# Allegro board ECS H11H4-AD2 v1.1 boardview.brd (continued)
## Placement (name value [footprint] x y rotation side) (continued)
TP15  tp  [TP30_SMD]  35.48 41.86 0 top
TP16  tp  [TP30_SMD]  33.91 40.72 90 top
TP17  tp  [TP30_SMD]  35.48 40 90 top
TP18  tp  [TP30_SMD]  35.43 38.05 0 top
TP19  tp  [TP30_SMD]  60.43 37.08 90 top
TP20  tp  [TP30_SMD]  99.92 35.56 0 top
U1  azc099-04s-r7g-s-o  [SOT23_6P_2]  171.55 233.48 270 top
U2  azc099-04s-r7g-s-o  [SOT23_6P_2]  178.66 233.38 90 top
U3  az1045-04f-s-o  [FPC_4P10_R_1]  118.72 228.73 0 top
U4  az1045-04f-s-o  [FPC_4P10_R_1]  122.78 228.73 0 top
U5  u74lvc1g32g-af5-r-o  [SOT23_5P_1]  168.07 228.19 90 top
U6  u74lvc1g32g-af5-r-o  [SOT23_5P_1]  172.62 228.19 90 top
U7  it6516afn_qfn-40-o  [QFN40_PT04_E2201]  188.24 227.89 0 top
U8  azc099-04s-r7g-s-o  [SOT23_6P_2]  130.4 227.33 90 top
U9  az1045-04f-s-o  [FPC_4P10_R_1]  140.56 226.82 0 top
U10  az1045-04f-s-o  [FPC_4P10_R_1]  136.12 226.8 0 top
U11  azc099-04s-r7g-s-o  [SOT23_6P_2]  149.96 226.26 90 top
U12  esd3v3u4ulc-o  [FPC_4P10_R_1]  94.97 223.6 0 top
U13  esd3v3u4ulc-o  [FPC_4P10_R_1]  99.42 223.49 0 top
U14  azc099-04s-r7g-s-o  [SOT23_6P_2]  90.88 222.96 0 top
U15  up7537bsu8s  [PSOP8_W150_PT50_PAD-UP7719B_1]  105.71 213.41 270 top
U16  azc099-04s-r7g-s-o  [SOT23_6P_2]  61.57 213.36 180 top
U17  az1013-04s  [SOT23_6P_2]  75.29 212.6 0 top
U18  az1013-04s  [SOT23_6P_2]  70.92 212.55 0 top
U19  isl95858hrz  [QFN52_PT04_NCP61X1S_1]  165.07 211.2 180 top
U20  up7536ama8s  [SOT23_8P_1]  76.43 202.31 270 top
U21  rtl8111ga-cg  [QFN32_PT04_NCP81102]  51.77 201.53 270 top
U22  up1537  [DFN10_PT05_RT8015A_1]  95.22 198.37 180 top
U23  74lvc1g08gws  [SOT353_5P]  28.68 183.46 90 top
U24  isl95808  [DFN8_PT05_ISL6208_1]  189.71 177.8 0 top
U25  up0104ssw8-o  [PSOP8_W150_PT50_PAD-UP6281_1]  5.94 156.84 0 top
U26  apl3529a  [DFN8_NCP5359A_1]  71.6 147.57 270 top
U27  isl95808  [DFN8_PT05_ISL6208_1]  191.11 142.37 0 top
U28  nb671  [FCQFN16_RT7290A_NB669]  62.43 124.18 90 top
U29  74lvc1g14gw-o  [SOT353_5P]  183.26 117.35 0 top
U30  up7536ama8s  [SOT23_8P_1]  15.85 75.56 0 top
U31  up1740p  [QFN32_PT04_UP1740Q_2]  144.37 73.28 180 top
U32  azc099-04s-r7g-s-o  [SOT23_6P_2]  9.35 69.85 270 top
U33  up7537bsu8s  [PSOP8_W150_PT50_PAD-UP7719B_1]  10.13 63.88 90 top
U34  gs358sfs-o  [SOP8_W150_PT50]  176.54 59.7 0 top
U35  up1537  [DFN10_PT05_RT8015A_1]  125.07 53.47 90 top
U36  up0104ssw8  [PSOP8_W150_PT50_PAD-UP6281_1]  158.98 49.91 0 top
U37  5v2305nrgi8s-o  [QFN16_PT05_2D1X2D6MM]  97.13 42.42 270 top
U38  it8613e-bx  [TQFP64_PT04_F71808A]  111.99 34.04 0 top
U39  azc099-04s-r7g-s-o  [SOT23_6P_2]  13.06 31.34 270 top
U40  up7536ama8s  [SOT23_8P_1]  20.29 25.15 0 top
U41  74lvc1g14gw  [SOT353_5P]  51.66 19.38 90 top
U42  azc099-04s-r7g-s-o  [SOT23_6P_2]  11.28 17.65 270 top
U43  74aup1g08gf-o  [SON6_SOT891_PT035_74AUP1G08]  79.35 15.37 270 top
USB2_LAN  usbx2-lan-1000-6k/2k-speedtech  [RJ45_USB_22P-ICOTHING_2]  76.74 231.03 180 top
USB3F1  h10x2-p20e-bk  [CON10X2_2MM_20P_USB3_1]  7.21 41.02 270 top
USB3X2  usb3x2-sb  [USB3_18P4R-LOTES-SHORTBODY_1]  101.65 237.17 180 top
VGA  conn-vga-stbl-o  [D-SUB_15P-HDR-HT]  180.8 240.53 0 top
WBT_LED  h4x1-wawh-p2.5-o  [J4X1_PT2D5MM-LONGSHOUNG_1]  33.05 17.62 180 top
X1  x-25m-30m20d  [CRYSTAL_PT4D88MM-AT49_2]  64.97 196.16 270 top
Y1  x-32.768k  [ETXTALS-SPAD_1]  39.49 33.6 180 top
Z1  jopen_200x60 mil  [JOPEN_200X60]  194.03 130.45 180 top
Z2  jopen_200x60-nmnp  [JOPEN_200X60-NMNP]  181.46 193.8 180 top
Z3  jopen_200x60-nmnp  [JOPEN_200X60-NMNP]  181.46 193.8 0 bottom

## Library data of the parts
A1 A2 = J2X1
ATX_12V = ATX_PWR_4P_2
ATX_POWER = ATX_PWR_24P_1
AUDIO = AUDIO_JACK_13P-COLAY_2
BAT1 = BATTERY_HOLDER_CR2032-LOTES
BOSS1-BOSS3 = HOLE_TC256BC180D165PT
BT1-BT3 = BAT54_132_2
BZ = BUZZER_1
C1 C5 C7-C10 C12-C16 C18-C22 C25 C26 C28-C38 C41-C43 C45-C49 C51-C53 C55-C68 C70-C83 C85-C95 C97 C101 C104 C105 C109 C110 C117-C131 C136-C149 C151 C152 C154-C156 C158 C166-C168 C170-C189 C193 C195-C207 C209-C213 C216-C222 C225-C230 C233 C235-C245 C255-C260 C262 C265 C266 C269 C270 C274 C275 C278 C279 C284 C288 C291 C297 C299 C305 C307 C309 C316-C318 C320 C321 C328 C332-C335 C340 C342 C343 C346-C349 C351-C357 C359-C364 C367 C370 C379 C382 C383 C387-C389 C391-C396 C401-C414 C416-C427 C429 C430 C442 C444 C445 C447-C449 C452-C454 C462 C464-C466 C468 C469 C472-C477 C480 C481 C485 C489 C492 C494 C496-C499 C504-C506 C509 C514-C516 C518 C521-C525 C527-C533 C535-C538 C548 C549 C551 C554-C557 C560-C562 C564-C578 C581-C586 C588-C602 C604-C609 C611-C614 C616-C623 C625-C637 C639 C640 C642-C644 C646 SC1-SC19 SC37 SC38 SC41-SC44 SC46-SC49 SC52 SC53 SC55-SC58 SC60-SC62 SC64-SC68 SC70 SC71 SC645 = C0402_2
C2 C4 C6 C11 C208 C215 C231 C232 C247-C254 C263 C264 C271 C272 C285 C289 C290 C298 C306 C310 C326 C336-C339 C344 C358 C384-C386 C390 C397 C400 C415 C432-C436 C439 C441 C443 C446 SC20 SC21 SC25 SC26 SC28 SC29 SC36 SC39 SC40 SC63 SC69 = C0603_4D7UF
C3 C39 C40 C133 C214 C286 C350 C381 C399 C437 C440 C467 C471 C482 C493 C510 C517 C534 C550 C558 C563 C580 C587 C603 C610 C615 C624 C638 C645 SC59 = C0603_2
C17 C23 C24 C27 C44 C50 C54 C69 C84 C96 C100 C132 C150 C153 C157 C169 C223 C224 C234 C246 C261 C267 C268 C273 C276 C277 C280-C283 C287 C292-C296 C300 C303 C304 C311 C314 C315 C319 C322-C325 C327 C329-C331 C341 C345 C368 C371 C380 C398 C428 C438 C457 C458 C470 C478 C479 C483 C484 C486-C488 C490 C491 C500 C501 C511-C513 C519 C520 C526 C539 C540 C545-C547 C552 C553 C559 C579 C641 SC23 SC24 SC27 SC31-SC34 SC45 SC50 SC51 SC54 = C0805_2
CHOKE1-CHOKE18 L7 L8 L25 L26 = WCM2012F2S_1
CLR_CMOS ME_DISABLE = J3X1
CMK1 L21 = CMM21_R0402
CMK2 CMK3 = CMM21_1
CODEC = LQFP48
CPU1 = LGA1151-INTEL
CPU_FAN SYS_FAN = J4X1_WAFER
D1 D2 D4 QN1 QN2 QN4-QN9 QN11-QN13 QN15-QN19 QN21-QN37 QN39 QN40 = SOT23_2MM_2
D3 D5 D6 D11 D13-D15 D17 D22-D25 = SOT23_3L
D7-D10 D12 = SOD_523
D16 D18 D21 = SOD_123_2
D19 D20 U3 U4 U9 U10 U12 U13 = FPC_4P10_R_1
DIMM1 DIMM2 = DDR3_240P_2
EC1-EC6 EC25 EC26 EC30-EC32 EC36 = EC2D5_6D3_H11MM
EC7-EC10 EC20 = EC3D5_8_H11MM_1P
EC11 = EC3D5_8_H11D5MM_1P
EC12-EC15 EC17-EC19 EC21-EC24 EC34 = EC2D5_6D3_H8MM
EC16 = EC200_260_SMD
EC27-EC29 = EC2D5_6D3_H9MM
EC33 EC35 = EC2D5_6D3_H12D5MM
F1 F2 = FUSE_SMD_1
F_AUDIO = J5X2_AUDIO_1
F_PANEL = J7X2_PANEL_10P
F_USB1 = J5X2_USB_1394
F_USB2 = J5X1_CR
FB1-FB3 PFB1-PFB4 PFB6 = FB0402_2
H1-H6 = HOLE8_5
HDMI1 HDMI2 = HDMI_19P-F_SMD-HIGH-TOP_5
L1-L6 L24 PFB10 = FB0603_2
L9 = L0805_2
L10 L20 PFB5 PFB7-PFB9 = FB0805_2
L11 = CHOKE_NLC252018_SMD_2P
L12 = CHOKE_9D5X11_PT7MM_H_2
L13 L14 L16-L18 = CHOKE_R30_PT6D3X1D4MM_1
L15 = CHOKE_PT3D5X5D5MM
L19 = CHOKE_PT5D45MM_SMD
L22 L23 = CHOKE_1R0M_PT6D6X4D8MM
LPC_DEBUG = J10X2_JLPC
M2_1 = CON75P_PT05_SMD_P24_31-LOTES
M2_2 = CON75P_PT05_SMD_B-LOTES
ME_TEST = J3X2
PCH1 = BGA837-INTEL_1
PCIE1X = PCIE_X1_36P_2
PCIE16X = PCIE_X16_164P_4
Q1-Q5 = SOT363_6P
Q6-Q10 Q13-Q21 Q24-Q26 Q31-Q40 Q44 SQ42 SQ43 = SOT23_BCE_2
Q11 = SOT_563_6P_1
Q22 = TO251_BCE_PT90_1
Q23 Q27-Q30 QN3 QN10 QN14 QSW1 = SOT23_GDS_2
QBH1 QBL1 QCGH1 QCGH2 QCGL1-QCGL4 QCH1-QCH3 QCL1-QCL6 QCSH1 QCSL1 = Q_TDSON8-GDS-4
QN20 = DFN6_PT065_SM2203NSQG
QSW2 U34 = SOP8_W150_PT50
R1-R10 R12 R16-R19 R21-R35 R37-R41 R43-R51 R56-R74 R77-R86 R88-R99 R101-R117 R119 R121-R123 R125 R128 R130 R134-R144 R146-R148 R151-R160 R162-R166 R168 R169 R171-R180 R182-R216 R218 R219 R222-R226 R228 R231-R233 R235 R237 R238 R241-R246 R248-R260 R262 R263 R265-R271 R273-R277 R279 R280 R282-R288 R290-R292 R294 R295 R297 R299 R300 R302 R303 R305-R312 R314-R316 R318 R319 R321-R328 R330-R361 R363-R377 R379-R383 R385-R390 R392-R394 R397-R404 R406-R418 R421-R445 R447-R456 R458-R468 R473 R475-R513 R515-R532 R534-R541 R543-R546 R549 R550 R552-R555 R557-R570 R572-R593 R595-R598 R600 R602-R614 R616 R619-R648 R650 R652-R667 R669-R739 R741-R753 R756-R759 R761-R763 RT1-RT4 SR1-SR17 SR20-SR36 SR765-SR768 = R0402_2
R11 R42 R100 R120 R131 R145 R167 R170 R181 R217 R220 R221 R227 R229 R230 R239 R240 R261 R264 R272 R278 R281 R293 R296 R298 R301 R304 R395 R419 R420 R457 R474 R514 R533 R542 = R0805_2
R118 R161 R236 R615 R740 = R0603-SHORT_1-NMNP
R124 R126 R132 R133 R149 R150 R247 R289 R317 R362 R378 R384 R396 R405 R446 R556 R571 R594 R599 R601 R649 R651 R754 R755 R760 R764 SR19 = R0603_2
R234 = R0603-SHORT_2
R313 R320 R329 R391 = R1206
R617 SP1-SP10 = SHORT2-NMNP
R618 = R0402-SHORT_2
R668 = R2512_1
RJ1 RJ3-RJ7 = RJ3_0402
RJ2 = RJ3_0805
RN1-RN7 RN9-RN11 RN13 = 8P4R
RN12 = 8P4R-0402
SATA1 SATA2 = SATA3_7P-HI-TOP
SC30 = C7343_1
SPI_DEBUG = J5X2_PT1D27MM_SMD_2P_1
SPIROM1 = SOP8_W210_PT50_SPI_1
STP1-STP4 STP6-STP9 STP12-STP17 STP22 STP24 STP26-STP74 TP3 TP5 TP8-TP20 = TP30_SMD
STP5 STP10 STP11 STP18-STP21 STP23 STP25 = TP4X20NP-BOT
SY1 = CRYSTAL_4P_PT2D2X1D6_SMD
U1 U2 U8 U11 U14 U16-U18 U32 U39 U42 = SOT23_6P_2
U5 U6 = SOT23_5P_1
U7 = QFN40_PT04_E2201
U15 U33 = PSOP8_W150_PT50_PAD-UP7719B_1
U19 = QFN52_PT04_NCP61X1S_1
U20 U30 U40 = SOT23_8P_1
U21 = QFN32_PT04_NCP81102
U22 U35 = DFN10_PT05_RT8015A_1
U23 U29 U41 = SOT353_5P
U24 U27 = DFN8_PT05_ISL6208_1
U25 U36 = PSOP8_W150_PT50_PAD-UP6281_1
U26 = DFN8_NCP5359A_1
U28 = FCQFN16_RT7290A_NB669
U31 = QFN32_PT04_UP1740Q_2
U37 = QFN16_PT05_2D1X2D6MM
U38 = TQFP64_PT04_F71808A
U43 = SON6_SOT891_PT035_74AUP1G08
USB2_LAN = RJ45_USB_22P-ICOTHING_2
USB3F1 = CON10X2_2MM_20P_USB3_1
USB3X2 = USB3_18P4R-LOTES-SHORTBODY_1
VGA = D-SUB_15P-HDR-HT
WBT_LED = J4X1_PT2D5MM-LONGSHOUNG_1
X1 = CRYSTAL_PT4D88MM-AT49_2
Y1 = ETXTALS-SPAD_1
Z1 = JOPEN_200X60
Z2 Z3 = JOPEN_200X60-NMNP

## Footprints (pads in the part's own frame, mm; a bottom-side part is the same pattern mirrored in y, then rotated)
8P4R
  rect 0.61x1.143 smd: 1(-1.219,-0.826) 2(-1.219,0.826) 7(1.219,-0.826) 8(1.219,0.826)
  rect 0.508x1.143 smd: 3(-0.406,-0.826) 4(-0.406,0.826) 5(0.406,-0.826) 6(0.406,0.826)
8P4R-0402
  rect 0.432x0.864 smd: 1(-0.826,-0.638) 2(-0.826,0.638) 7(0.826,-0.638) 8(0.826,0.638)
  rect 0.279x0.864 smd: 3(-0.25,-0.638) 4(-0.25,0.638) 5(0.25,-0.638) 6(0.25,0.638)
ATX_PWR_4P_2
  rect 2.286x2.286 hole 1.422: 1(-2.1,2.8)
  round 2.286 hole 1.422: 2(2.1,2.8) 3(-2.1,-2.8) 4(2.1,-2.8)
ATX_PWR_24P_1
  rect 1.905x1.905 hole 1.397: 1(2.75,23.1)
  round 1.905 hole 1.397: 2(2.75,18.9) 3(2.75,14.7) 4(2.75,10.5) 5(2.75,6.3) 6(2.75,2.1) 7(2.75,-2.1) 8(2.75,-6.3) 9(2.75,-10.5) 10(2.75,-14.7) 11(2.75,-18.9) 12(2.75,-23.1) 13(-2.75,23.1) 14(-2.75,18.9) 15(-2.75,14.7) 16(-2.75,10.5) 17(-2.75,6.3) 18(-2.75,2.1) 19(-2.75,-2.1) 20(-2.75,-6.3) 21(-2.75,-10.5) 22(-2.75,-14.7) 23(-2.75,-18.9) 24(-2.75,-23.1)
AUDIO_JACK_13P-COLAY_2
  round 2.337 hole 2.337 unplated: (0,5.275)
  oval 1.473x1.575 hole 1.016x1.118: 5(0,1.425) 11(5,1.425) 12(2.5,1.425) 13(-2.5,1.425) 14(-5,1.425) 21(3.75,-3.575) 22(1.25,-3.575) 23(-1.25,-3.575) 24(-3.75,-3.575) 31(3.75,-8.575) 32(1.25,-8.575) 33(-1.25,-8.575) 34(-3.75,-8.575)
  round 2.692 hole 2.337: G1(-6.05,5.275) G2(6.05,5.275) G3(-6.05,-6.025) G4(6.05,-6.025)
BAT54_132_2
  rect 1.016x1.016 smd: 1(-1.016,-1.143) 2(1.016,-1.143) 3(0,1.143)
BATTERY_HOLDER_CR2032-LOTES
  round 1.524 hole 1.016: N(0,7.71)
  round 1.626 hole 1.118: P(0,-12.29)
BGA837-INTEL_1
  round 1.016 smd: (-12.548,-12.548) (12.636,12.764)
  round 0.305 smd: A2(10.46,-10.814) A3(9.959,-10.814) A4(9.459,-10.814) A42(-9.459,-10.814) A43(-9.959,-10.814) A44(-10.46,-10.814) AA17(3.099,-0.775) AA18(2.324,-0.775) AA20(1.549,-0.775) AA21(0.775,-0.775) AA23(0,-0.775) AA25(-0.775,-0.775) AA26(-1.549,-0.775) AA28(-2.324,-0.775) AA29(-3.099,-0.775) AB7(8.175,-0.667) AB8(7.413,-0.667) AB10(6.651,-0.667) AB11(5.889,-0.667) AB13(5.127,-0.667) AB14(4.365,-0.667) AB15(3.807,-0.667) AB31(-3.807,-0.667) AB32(-4.365,-0.667) AB33(-5.127,-0.667) AB35(-5.889,-0.667) AB36(-6.651,-0.667) AB38(-7.413,-0.667) AB39(-8.175,-0.667) AC17(3.099,0) AC18(2.324,0) AC20(1.549,0) AC21(0.775,0) AC23(0,0) AC25(-0.775,0) AC26(-1.549,0) AC28(-2.324,0) AC29(-3.099,0) AD7(8.175,0.667) AD8(7.413,0.667) AD10(6.651,0.667) AD11(5.889,0.667) AD13(5.127,0.667) AD14(4.365,0.667) AD15(3.807,0.667) AD31(-3.807,0.667) AD32(-4.365,0.667) AD33(-5.127,0.667) AD35(-5.889,0.667) AD36(-6.651,0.667) AD38(-7.413,0.667) AD39(-8.175,0.667) AE17(3.099,0.775) AE18(2.324,0.775) AE20(1.549,0.775) AE21(0.775,0.775) AE23(0,0.775) AE25(-0.775,0.775) AE26(-1.549,0.775) AE28(-2.324,0.775) AE29(-3.099,0.775) AF17(3.099,1.549) AF18(2.324,1.549) AF20(1.549,1.549) AF21(0.775,1.549) AF23(0,1.549) AF25(-0.775,1.549) AF26(-1.549,1.549) AF28(-2.324,1.549) AF29(-3.099,1.549) AG7(8.175,1.772) AG8(7.413,1.772) AG10(6.651,1.772) AG11(5.889,1.772) AG13(5.127,1.772) AG14(4.365,1.772) AG15(3.807,1.772) AG31(-3.807,1.772) AG32(-4.365,1.772) AG33(-5.127,1.772) AG35(-5.889,1.772) AG36(-6.651,1.772) AG38(-7.413,1.772) AG39(-8.175,1.772) AH17(3.099,2.324) AH18(2.324,2.324) AH20(1.549,2.324) AH21(0.775,2.324) AH23(0,2.324) AH25(-0.775,2.324) AH26(-1.549,2.324) AH28(-2.324,2.324) AH29(-3.099,2.324) AJ7(8.074,2.953) AJ8(7.312,2.953) AJ10(6.55,2.953) AJ11(5.788,2.953) AJ13(5.026,2.953) AJ14(4.315,2.953) AJ15(3.807,2.953) AJ17(3.099,3.099) AJ18(2.324,3.099) AJ20(1.549,3.099) AJ21(0.775,3.099) AJ23(0,3.099) AJ25(-0.775,3.099) AJ26(-1.549,3.099) AJ28(-2.324,3.099) AJ29(-3.099,3.099) AJ31(-3.807,2.953) AJ32(-4.365,2.953) AJ33(-5.127,2.953) AJ35(-5.889,2.953) AJ36(-6.651,2.953) AJ38(-7.413,2.953) AJ39(-8.175,2.953) AL7(8.074,4.071) AL8(7.312,4.071) AL10(6.55,4.071) AL11(5.788,4.071) AL13(5.026,4.071) AL17(2.953,3.807) AL19(1.772,3.807) AL22(0.667,3.807) AL24(-0.667,3.807) AL27(-1.772,3.807) AL29(-2.953,3.807) AL32(-4.34,4.096) AL33(-5.102,4.096) AL35(-5.864,4.096) AL36(-6.626,4.096) AL38(-7.388,4.096) AL39(-8.15,4.096) AM15(4.096,4.34) AM17(2.953,4.365) AM19(1.772,4.365) AM22(0.667,4.365) AM24(-0.667,4.365) AM27(-1.772,4.365) AM29(-2.953,4.315) AN7(8.023,5.036) AN8(7.261,4.985) AN10(6.499,4.985) AN11(5.753,5.026) AN15(4.096,5.102) AN17(2.953,5.127) AN19(1.772,5.127) AN22(0.667,5.127) AN24(-0.667,5.127) AN27(-1.772,5.127) AN29(-2.953,5.026) AN31(-4.071,5.026) AN36(-6.47,5.087) AN38(-7.232,5.087) AN39(-7.994,5.087) AP11(6.04,5.551) AR7(7.999,6.037) AR9(7.084,6.077) AR15(4.096,5.864) AR17(2.953,5.889) AR19(1.772,5.889) AR22(0.667,5.889) AR24(-0.667,5.889) AR27(-1.772,5.889) AR29(-2.953,5.788) AR31(-4.071,5.788) AR33(-5.026,5.753) AR34(-5.551,6.04) AR38(-7.396,6.068) AR39(-8.158,6.068) AT9(6.938,6.713) AT10(6.311,6.663) AT13(5.087,6.47) AT15(4.096,6.626) AT17(2.953,6.651) AT19(1.772,6.651) AT22(0.667,6.651) AT24(-0.667,6.651) AT27(-1.772,6.651) AT29(-2.953,6.55) AT31(-4.071,6.55) AT33(-4.985,6.499) AT36(-6.663,6.311) AU7(7.936,6.994) AU35(-6.077,7.084) AU36(-6.713,6.938) AU39(-7.991,7.141) AV6(8.237,7.645) AV11(6.068,7.396) AV13(5.087,7.232) AV15(4.096,7.388) AV17(2.953,7.413) AV19(1.772,7.413) AV22(0.667,7.413) AV24(-0.667,7.413) AV27(-1.772,7.413) AV29(-2.953,7.312) AV31(-4.071,7.312) AV33(-4.985,7.261) AW9(7.141,7.991) AW11(6.068,8.158) AW13(5.087,7.994) AW15(4.096,8.15) AW17(2.953,8.175) AW19(1.772,8.175) AW22(0.667,8.175) AW24(-0.667,8.175) AW27(-1.772,8.175) AW29(-2.953,8.074) AW31(-4.071,8.074) AW33(-5.036,8.023) AW35(-6.037,7.999) AW37(-6.994,7.936) AY5(8.764,8.585) AY38(-7.645,8.237) B1(10.814,-10.46) B2(10.33,-10.33) B3(9.824,-10.326) B43(-9.8,-10.304) B44(-10.33,-10.33) B45(-10.814,-10.46) BA40(-8.585,8.764) BB1(10.814,9.459) BB45(-10.814,9.459) BC1(10.814,9.959) BC2(10.326,9.824) BC44(-10.304,9.8) BC45(-10.814,9.959) BD1(10.814,10.46) BD2(10.33,10.33) BD3(9.8,10.304) BD43(-9.824,10.326) BD44(-10.33,10.33) BD45(-10.814,10.46) BE2(10.46,10.814) BE3(9.959,10.814) BE4(9.459,10.814) BE42(-9.459,10.814) BE43(-9.959,10.814) BE44(-10.46,10.814) C1(10.814,-9.959) C2(10.304,-9.8) C42(-9.288,-9.86) C44(-10.326,-9.824) C45(-10.814,-9.959) D1(10.814,-9.459) D45(-10.814,-9.459) F8(7.645,-8.237) G9(6.994,-7.936) G11(6.037,-7.999) G13(5.036,-8.023) G15(4.071,-8.074) G17(2.953,-8.074) G19(1.772,-8.175) G22(0.667,-8.175) G24(-0.667,-8.175) G27(-1.772,-8.175) G29(-2.953,-8.175) G31(-4.096,-8.15) G33(-5.087,-7.994) G35(-6.068,-8.158) G37(-7.141,-7.991) H13(4.985,-7.261) H15(4.071,-7.312) H17(2.953,-7.312) H19(1.772,-7.413) H22(0.667,-7.413) H24(-0.667,-7.413) H27(-1.772,-7.413) H29(-2.953,-7.413) H31(-4.096,-7.388) H33(-5.087,-7.232) H35(-6.068,-7.396) J7(7.991,-7.141) J10(6.713,-6.938) J11(6.077,-7.084) J39(-7.936,-6.994) K10(6.663,-6.311) K13(4.985,-6.499) K15(4.071,-6.55) K17(2.953,-6.55) K19(1.772,-6.651) K22(0.667,-6.651) K24(-0.667,-6.651) K27(-1.772,-6.651) K29(-2.953,-6.651) K31(-4.096,-6.626) K33(-5.087,-6.47) K36(-6.311,-6.663) K37(-6.938,-6.713) L7(8.158,-6.068) L8(7.396,-6.068) L12(5.551,-6.04) L13(5.026,-5.753) L15(4.071,-5.788) L17(2.953,-5.788) L19(1.772,-5.889) L22(0.667,-5.889) L24(-0.667,-5.889) L27(-1.772,-5.889) L29(-2.953,-5.889) L31(-4.096,-5.864) L37(-7.084,-6.077) L39(-7.999,-6.037) M35(-6.04,-5.551) N7(7.994,-5.087) N8(7.232,-5.087) N10(6.47,-5.087) N15(4.071,-5.026) N17(2.953,-5.026) N19(1.772,-5.127) N22(0.667,-5.127) N24(-0.667,-5.127) N27(-1.772,-5.127) N29(-2.953,-5.127) N31(-4.096,-5.102) N35(-5.753,-5.026) N36(-6.499,-4.985) N38(-7.261,-4.985) N39(-8.023,-5.036) P17(2.953,-4.315) P19(1.772,-4.365) P22(0.667,-4.365) P24(-0.667,-4.365) P27(-1.772,-4.365) P29(-2.953,-4.365) P31(-4.096,-4.34) R7(8.15,-4.096) R8(7.388,-4.096) R10(6.626,-4.096) R11(5.864,-4.096) R13(5.102,-4.096) R14(4.34,-4.096) R17(2.953,-3.807) R19(1.772,-3.807) R22(0.667,-3.807) R24(-0.667,-3.807) R27(-1.772,-3.807) R29(-2.953,-3.807) R33(-5.026,-4.071) R35(-5.788,-4.071) R36(-6.55,-4.071) R38(-7.312,-4.071) R39(-8.074,-4.071) U7(8.175,-2.953) U8(7.413,-2.953) U10(6.651,-2.953) U11(5.889,-2.953) U13(5.127,-2.953) U14(4.365,-2.953) U15(3.807,-2.953) U17(3.099,-3.099) U18(2.324,-3.099) U20(1.549,-3.099) U21(0.775,-3.099) U23(0,-3.099) U25(-0.775,-3.099) U26(-1.549,-3.099) U28(-2.324,-3.099) U29(-3.099,-3.099) U31(-3.807,-2.953) U32(-4.315,-2.953) U33(-5.026,-2.953) U35(-5.788,-2.953) U36(-6.55,-2.953) U38(-7.312,-2.953) U39(-8.074,-2.953) V17(3.099,-2.324) V18(2.324,-2.324) V20(1.549,-2.324) V21(0.775,-2.324) V23(0,-2.324) V25(-0.775,-2.324) V26(-1.549,-2.324) V28(-2.324,-2.324) V29(-3.099,-2.324) W7(8.175,-1.772) W8(7.413,-1.772) W10(6.651,-1.772) W11(5.889,-1.772) W13(5.127,-1.772) W14(4.365,-1.772) W15(3.807,-1.772) W31(-3.807,-1.772) W32(-4.365,-1.772) W33(-5.127,-1.772) W35(-5.889,-1.772) W36(-6.651,-1.772) W38(-7.413,-1.772) W39(-8.175,-1.772) Y17(3.099,-1.549) Y18(2.324,-1.549) Y20(1.549,-1.549) Y21(0.775,-1.549) Y23(0,-1.549) Y25(-0.775,-1.549) Y26(-1.549,-1.549) Y28(-2.324,-1.549) Y29(-3.099,-1.549)
  round 0.279 smd: A5(8.959,-10.814) A41(-8.959,-10.814) BA1(10.814,8.959) BA45(-10.814,8.959) BE5(8.959,10.814) BE41(-8.959,10.814) E1(10.814,-8.959) E45(-10.814,-8.959)
  round 0.254 smd: A6(8.458,-10.814) A25(-1.225,-10.814) A40(-8.458,-10.814) AB3(9.888,-0.609) AB4(9.403,-0.482) AB5(8.937,-0.667) AB41(-8.937,-0.667) AB42(-9.421,-0.509) AC3(9.727,-0.096) AD3(9.929,0.484) AD4(9.421,0.509) AD5(8.937,0.667) AD41(-8.937,0.667) AD42(-9.403,0.482) AF3(9.888,1.664) AF5(8.885,1.721) AF41(-8.887,1.721) AG3(9.727,2.178) AG4(9.403,1.791) AG42(-9.421,1.764) AJ4(9.421,2.783) AJ5(8.836,2.953) AJ41(-8.937,2.953) AJ42(-9.403,2.756) AL3(9.888,3.937) AL4(9.403,4.064) AL5(8.836,4.071) AL41(-8.887,4.096) AL42(-9.421,4.037) AM3(9.727,4.451) AN3(9.929,5.03) AN4(9.421,5.056) AN5(8.785,5.163) AN41(-8.756,5.087) AN42(-9.403,5.029) AR5(8.886,6.182) AR41(-8.92,6.068) AT4(9.403,6.338) AT42(-9.421,6.311) AU41(-9.038,7.09) AU43(-9.727,6.915) AV3(9.929,7.355) AV4(9.229,7.321) AV43(-9.888,7.391) AW4(9.434,8.204) AW42(-9.24,7.816) AY1(10.814,8.458) AY45(-10.814,8.458) B6(8.45,-10.296) B10(6.724,-10.235) B25(-1.225,-10.306) B40(-8.701,-10.355) BA4(9.602,9.12) BA5(8.767,9.095) BA9(7.09,9.038) BA11(6.068,8.92) BA13(5.087,8.756) BA15(4.096,8.887) BA17(2.953,8.937) BA20(1.721,8.887) BA22(0.667,8.937) BA24(-0.667,8.937) BA26(-1.721,8.885) BA29(-2.953,8.836) BA31(-4.071,8.836) BA33(-5.163,8.785) BA35(-6.182,8.886) BA41(-9.095,8.767) BB3(10.162,9.344) BB7(7.816,9.24) BB10(6.311,9.421) BB13(5.029,9.403) BB15(4.037,9.421) BB17(2.756,9.403) BB19(1.764,9.421) BB22(0.482,9.403) BB24(-0.509,9.421) BB27(-1.791,9.403) BB29(-2.783,9.421) BB31(-4.064,9.403) BB33(-5.056,9.421) BB36(-6.338,9.403) BB38(-7.321,9.229) BB39(-8.204,9.434) BB41(-9.12,9.602) BB43(-9.86,9.288) BC4(9.288,9.86) BC9(6.915,9.727) BC42(-9.344,10.162) BE6(8.458,10.814) BE40(-8.458,10.814) C8(7.355,-9.929) C10(6.724,-9.727) C11(6.211,-9.888) C14(4.451,-9.727) C15(3.937,-9.888) C17(2.757,-9.929) C19(2.178,-9.727) C20(1.664,-9.888) C23(-0.096,-9.727) C24(-0.609,-9.888) C27(-1.789,-9.929) C28(-2.369,-9.727) C29(-2.883,-9.888) C31(-4.063,-9.929) C32(-4.642,-9.727) C33(-5.156,-9.888) C36(-6.336,-9.929) C37(-6.915,-9.727) C38(-7.391,-9.888) D3(9.86,-9.288) D5(9.12,-9.602) D7(8.204,-9.434) D8(7.321,-9.229) D10(6.338,-9.403) D13(5.056,-9.421) D15(4.064,-9.403) D17(2.783,-9.421) D19(1.791,-9.403) D22(0.509,-9.421) D24(-0.482,-9.403) D27(-1.764,-9.421) D29(-2.756,-9.403) D31(-4.037,-9.421) D33(-5.029,-9.403) D36(-6.311,-9.421) D39(-7.816,-9.24) D43(-10.162,-9.344) E5(9.095,-8.767) E6(8.585,-8.764) E11(6.182,-8.886) E13(5.163,-8.785) E15(4.071,-8.836) E17(2.953,-8.836) E20(1.721,-8.885) E22(0.667,-8.937) E24(-0.667,-8.937) E26(-1.721,-8.887) E29(-2.953,-8.937) E31(-4.096,-8.887) E33(-5.087,-8.756) E35(-6.068,-8.92) E37(-7.09,-9.038) E41(-8.767,-9.095) E42(-9.602,-9.12) F1(10.814,-8.458) F41(-8.764,-8.585) F44(-10.296,-8.45) F45(-10.814,-8.458) G4(9.24,-7.816) G42(-9.434,-8.204) H2(10.396,-7.391) H3(9.888,-7.391) H40(-8.237,-7.645) H42(-9.229,-7.321) H43(-9.929,-7.355) J2(10.235,-6.915) J3(9.727,-6.915) J5(9.038,-7.09) K2(10.428,-6.432) K3(9.929,-6.336) K4(9.421,-6.311) K42(-9.403,-6.338) K43(-9.727,-6.724) L5(8.92,-6.068) L41(-8.886,-6.182) L43(-9.888,-6.211) N3(9.888,-5.156) N4(9.403,-5.029) N5(8.756,-5.087) N41(-8.785,-5.163) N42(-9.421,-5.056) P3(9.727,-4.642) R4(9.421,-4.037) R5(8.887,-4.096) R41(-8.836,-4.071) R42(-9.403,-4.064) U3(9.888,-2.883) U4(9.403,-2.756) U5(8.937,-2.953) U41(-8.836,-2.953) U42(-9.421,-2.783) V3(9.727,-2.369) W3(9.929,-1.789) W4(9.421,-1.764) W42(-9.403,-1.791) Y5(8.887,-1.721) Y41(-8.885,-1.721)
  oval 0.203x0.254 smd: A7(7.893,-10.814) A9(6.852,-10.814) A37(-6.839,-10.814) A39(-7.893,-10.814) B7(7.944,-10.306) B39(-7.944,-10.306) BC8(7.391,9.888) BD6(8.701,10.355) BD7(7.944,10.306) BD36(-6.724,10.235) BD39(-7.944,10.306) BE7(7.893,10.814) BE9(6.839,10.814) BE37(-6.852,10.814) BE39(-7.893,10.814)
  oval 0.152x0.254 smd: A12(5.595,-10.814) A14(4.553,-10.814) A16(3.321,-10.814) A18(2.28,-10.814) A21(1.048,-10.814) A23(0.007,-10.814) A28(-2.267,-10.814) A32(-4.54,-10.814) B8(7.258,-10.428) B11(6.211,-10.396) B13(4.934,-10.428) B15(3.937,-10.396) B18(2.661,-10.428) B19(2.178,-10.235) B20(1.664,-10.396) B22(0.388,-10.428) B24(-0.609,-10.396) B27(-1.886,-10.428) B33(-5.156,-10.396) B36(-6.432,-10.428) BD10(6.432,10.428) BD13(5.156,10.396) BD14(4.642,10.235) BD15(4.159,10.428) BD17(2.883,10.396) BD18(2.369,10.235) BD19(1.886,10.428) BD22(0.609,10.396) BD23(0.096,10.235) BD24(-0.388,10.428) BD26(-1.664,10.396) BD27(-2.178,10.235) BD28(-2.661,10.428) BD31(-3.937,10.396) BD32(-4.451,10.235) BD33(-4.934,10.428) BD35(-6.211,10.396) BD38(-7.258,10.428) BE11(5.772,10.814) BE14(4.54,10.814) BE16(3.499,10.814) BE18(2.267,10.814) BE21(1.225,10.814) BE23(-0.007,10.814) BE25(-1.048,10.814) BE28(-2.28,10.814) BE30(-3.321,10.814) BE32(-4.553,10.814) BE34(-5.595,10.814)
  custom 0.051x0.051 smd: A30(-3.499,-10.814) A35(-5.772,-10.814) AA2(10.306,-1.225) AA44(-10.306,-1.048) AB43(-9.929,-0.484) AD43(-9.888,0.609) AE2(10.306,1.048) AE44(-10.306,1.225) AG43(-9.929,1.789) AJ3(9.929,2.757) AJ43(-9.888,2.883) AK2(10.306,3.321) AK44(-10.306,3.499) AL43(-9.929,4.063) AM2(10.235,4.451) AN43(-9.888,5.156) AP2(10.306,5.595) AR3(9.888,6.211) AR44(-10.306,5.772) AT43(-9.929,6.336) AU44(-10.235,6.915) AV44(-10.396,7.391) B12(5.595,-10.306) B14(4.451,-10.235) B16(3.321,-10.306) B21(1.048,-10.306) B23(-0.096,-10.235) B29(-2.883,-10.396) B30(-3.499,-10.306) B31(-4.159,-10.428) B32(-4.642,-10.235) B35(-5.772,-10.306) B37(-6.915,-10.235) B38(-7.391,-10.396) BC10(6.336,9.929) BC13(5.156,9.888) BC15(4.063,9.929) BC17(2.883,9.888) BC19(1.789,9.929) BC22(0.609,9.888) BC24(-0.484,9.929) BC26(-1.664,9.888) BC29(-2.757,9.929) BC31(-3.937,9.888) BC33(-5.03,9.929) BC35(-6.211,9.888) BC38(-7.355,9.929) BD8(7.391,10.396) BD9(6.915,10.235) BD11(5.772,10.306) BD16(3.499,10.306) BD21(1.225,10.306) BD25(-1.048,10.306) BD30(-3.321,10.306) BD34(-5.595,10.306) C13(5.03,-9.929) C22(0.484,-9.929) L2(10.306,-5.772) M44(-10.306,-5.595) N43(-9.929,-5.03) P2(10.235,-4.642) R2(10.428,-4.159) R3(9.929,-4.063) R43(-9.888,-3.937) T1(10.814,-3.499) T2(10.306,-3.499) T44(-10.306,-3.321) U2(10.396,-2.883) U43(-9.929,-2.757) V2(10.235,-2.369) Y43(-9.888,-1.664)
  oval 0.254x0.152 smd: AA1(10.814,-1.225) AA45(-10.814,-1.048) AB2(10.396,-0.609) AB44(-10.428,-0.388) AC1(10.814,0.007) AC2(10.235,-0.096) AC44(-10.235,0.096) AC45(-10.814,-0.007) AD2(10.428,0.388) AD44(-10.396,0.609) AE1(10.814,1.048) AE45(-10.814,1.225) AF2(10.396,1.664) AG2(10.235,2.178) AG44(-10.428,1.886) AH1(10.814,2.28) AH2(10.428,2.661) AH44(-10.235,2.369) AH45(-10.814,2.267) AJ44(-10.396,2.883) AK1(10.814,3.321) AK45(-10.814,3.499) AL2(10.396,3.937) AL44(-10.428,4.159) AM1(10.814,4.553) AM44(-10.235,4.642) AM45(-10.814,4.54) AN2(10.428,4.934) AN44(-10.396,5.156) AP1(10.814,5.595) AR2(10.396,6.211) AR45(-10.814,5.772) AT44(-10.428,6.432) AV2(10.428,7.258) L1(10.814,-5.772) L44(-10.396,-6.211) M45(-10.814,-5.595) N2(10.396,-5.156) N44(-10.428,-4.934) P1(10.814,-4.54) P44(-10.235,-4.451) P45(-10.814,-4.553) R44(-10.396,-3.937) T45(-10.814,-3.321) V1(10.814,-2.267) V44(-10.428,-2.661) V45(-10.814,-2.28) W2(10.428,-1.886) W44(-10.235,-2.178) Y44(-10.396,-1.664)
  round 0.368 smd: AA4(9.326,-1.225) AA42(-9.324,-1.048) AE4(9.324,1.048) AE42(-9.326,1.225) AK4(9.324,3.321) AK42(-9.326,3.499) AP4(9.324,5.595) AR42(-9.326,5.772) AY2(10.296,8.45) BB11(5.772,9.326) BB16(3.499,9.326) BB21(1.225,9.326) BB25(-1.048,9.324) BB30(-3.321,9.324) BB34(-5.595,9.324) BD40(-8.45,10.296) C4(9.344,-10.162) D12(5.595,-9.324) D16(3.321,-9.324) D21(1.048,-9.324) D25(-1.225,-9.326) D30(-3.499,-9.326) D35(-5.772,-9.326) L4(9.326,-5.772) M42(-9.324,-5.595) T4(9.326,-3.499) T42(-9.324,-3.321)
  custom 0.057x0.057 smd: AC43(-9.727,0.096) AH43(-9.727,2.369) AM43(-9.727,4.642) AT3(9.727,6.724) B28(-2.369,-10.235) BC14(4.642,9.727) BC18(2.369,9.727) BC23(0.096,9.727) BC27(-2.178,9.727) BC32(-4.451,9.727) BC36(-6.724,9.727) P43(-9.727,-4.451) W43(-9.727,-2.178)
  oval 0.254x0.203 smd: AT2(10.235,6.724) AU1(10.814,6.852) AU45(-10.814,6.839) AW1(10.814,7.893) AW2(10.306,7.944) AW44(-10.306,7.944) AW45(-10.814,7.893) AY44(-10.355,8.701) F2(10.355,-8.701) G1(10.814,-7.893) G2(10.306,-7.944) G44(-10.306,-7.944) G45(-10.814,-7.893) H44(-10.428,-7.258) J1(10.814,-6.839) J45(-10.814,-6.852) K44(-10.235,-6.724)
BUZZER_1
  round 1.372 hole 0.914: N(3.251,0) P(-3.251,0)
C0402_2
  oval 0.572x0.508 smd: 1(-0.476,0) 2(0.476,0)
C0603_2
  oval 0.889x0.762 smd: 1(-0.699,0) 2(0.699,0)
C0603_4D7UF
  oval 0.991x0.864 smd: 1(-0.699,0) 2(0.699,0)
C0805_2
  oval 1.016x1.397 smd: 1(-0.889,0) 2(0.889,0)
C7343_1
  rect 2.55x2.9 smd: 1(-3.125,0) 2(3.125,0)
CHOKE_1R0M_PT6D6X4D8MM
  round 2.388 hole 1.93: 1(-3.3,2.4)
  oval 2.845x2.388 hole 2.388x1.93 rot 135: 2(3.3,-2.4)
CHOKE_9D5X11_PT7MM_H_2
  oval 1.981x2.438 hole 1.524x1.981: 1(-3.5,0)
  oval 2.438x1.981 hole 1.981x1.524: 2(3.5,0)
CHOKE_NLC252018_SMD_2P
  rect 1.02x2.54 smd: 1(-1.145,0) 2(1.145,0)
CHOKE_PT3D5X5D5MM
  round 1.981 hole 1.524: 1(-1.75,2.65)
  oval 2.438x1.981 hole 1.981x1.524 rot 135: 2(1.75,-2.85)
CHOKE_PT5D45MM_SMD
  rect 2.95x3.5 smd: 1(-2.725,0) 2(2.725,0)
CHOKE_R30_PT6D3X1D4MM_1
  round 2.286 hole 1.829: 1(3.15,0.7)
  oval 2.286x2.743 hole 1.829x2.286 rot 135: 2(-3.15,-0.7)
CMM21_1
  rect 0.45x0.9 smd: 1(-0.425,0.85) 2(-0.425,-0.85) 3(0.425,-0.85) 4(0.425,0.85)
CMM21_R0402
  custom 0.127x0.127 smd: 1(-0.504,0.745) 2(-0.504,-0.745) 3(0.504,-0.745) 4(0.504,0.745)
CON10X2_2MM_20P_USB3_1
  rect 1.168x1.168 hole 0.813: 1(-9,1)
  round 1.168 hole 0.813: 2(-7,1) 3(-5,1) 4(-3,1) 5(-1,1) 6(1,1) 7(3,1) 8(5,1) 9(7,1) 10(9,1) 11(9,-1) 12(7,-1) 13(5,-1) 14(3,-1) 15(1,-1) 16(-1,-1) 17(-3,-1) 18(-5,-1) 19(-7,-1)
CON75P_PT05_SMD_B-LOTES
  round 1.118 hole 1.118 unplated: (-10,-1.425)
  round 1.626 hole 1.626 unplated: (10,-1.425)
  rect 0.279x1.575 smd: 1(-9.25,3.85) 2(-9,-3.7) 3(-8.75,3.85) 4(-8.5,-3.7) 5(-8.25,3.85) 6(-8,-3.7) 7(-7.75,3.85) 8(-7.5,-3.7) 9(-7.25,3.85) 10(-7,-3.7) 11(-6.75,3.85) 20(-4.5,-3.7) 21(-4.25,3.85) 22(-4,-3.7) 23(-3.75,3.85) 24(-3.5,-3.7) 25(-3.25,3.85) 26(-3,-3.7) 27(-2.75,3.85) 28(-2.5,-3.7) 29(-2.25,3.85) 30(-2,-3.7) 31(-1.75,3.85) 32(-1.5,-3.7) 33(-1.25,3.85) 34(-1,-3.7) 35(-0.75,3.85) 36(-0.5,-3.7) 37(-0.25,3.85) 38(0,-3.7) 39(0.25,3.85) 40(0.5,-3.7) 41(0.75,3.85) 42(1,-3.7) 43(1.25,3.85) 44(1.5,-3.7) 45(1.75,3.85) 46(2,-3.7) 47(2.25,3.85) 48(2.5,-3.7) 49(2.75,3.85) 50(3,-3.7) 51(3.25,3.85) 52(3.5,-3.7) 53(3.75,3.85) 54(4,-3.7) 55(4.25,3.85) 56(4.5,-3.7) 57(4.75,3.85) 58(5,-3.7) 59(5.25,3.85) 60(5.5,-3.7) 61(5.75,3.85) 62(6,-3.7) 63(6.25,3.85) 64(6.5,-3.7) 65(6.75,3.85) 66(7,-3.7) 67(7.25,3.85) 68(7.5,-3.7) 69(7.75,3.85) 70(8,-3.7) 71(8.25,3.85) 72(8.5,-3.7) 73(8.75,3.85) 74(9,-3.7) 75(9.25,3.85)
  rect 1.2x2.75 smd: 76(-10.35,3.075) 77(10.35,3.075)
CON75P_PT05_SMD_P24_31-LOTES
  round 1.118 hole 1.118 unplated: (-10,-1.5)
  round 1.626 hole 1.626 unplated: (10,-1.5)
  rect 0.279x1.575 smd: 1(-9.25,3.775) 2(-9,-3.775) 3(-8.75,3.775) 4(-8.5,-3.775) 5(-8.25,3.775) 6(-8,-3.775) 7(-7.75,3.775) 8(-7.5,-3.775) 9(-7.25,3.775) 10(-7,-3.775) 11(-6.75,3.775) 12(-6.5,-3.775) 13(-6.25,3.775) 14(-6,-3.775) 15(-5.75,3.775) 16(-5.5,-3.775) 17(-5.25,3.775) 18(-5,-3.775) 19(-4.75,3.775) 20(-4.5,-3.775) 21(-4.25,3.775) 22(-4,-3.775) 23(-3.75,3.775) 32(-1.5,-3.775) 33(-1.25,3.775) 34(-1,-3.775) 35(-0.75,3.775) 36(-0.5,-3.775) 37(-0.25,3.775) 38(0,-3.775) 39(0.25,3.775) 40(0.5,-3.775) 41(0.75,3.775) 42(1,-3.775) 43(1.25,3.775) 44(1.5,-3.775) 45(1.75,3.775) 46(2,-3.775) 47(2.25,3.775) 48(2.5,-3.775) 49(2.75,3.775) 50(3,-3.775) 51(3.25,3.775) 52(3.5,-3.775) 53(3.75,3.775) 54(4,-3.775) 55(4.25,3.775) 56(4.5,-3.775) 57(4.75,3.775) 58(5,-3.775) 59(5.25,3.775) 60(5.5,-3.775) 61(5.75,3.775) 62(6,-3.775) 63(6.25,3.775) 64(6.5,-3.775) 65(6.75,3.775) 66(7,-3.775) 67(7.25,3.775) 68(7.5,-3.775) 69(7.75,3.775) 70(8,-3.775) 71(8.25,3.775) 72(8.5,-3.775) 73(8.75,3.775) 74(9,-3.775) 75(9.25,3.775)
  rect 1.2x2.75 smd: 76(-10.35,3) 77(10.35,3)
CRYSTAL_4P_PT2D2X1D6_SMD
  rect 1.422x1.219 smd: 1(-1.1,-0.8) 2(1.1,-0.8) 3(1.1,0.8) 4(-1.1,0.8)
CRYSTAL_PT4D88MM-AT49_2
  round 1.219 hole 0.838: 1(-2.44,0) 2(2.44,0)
  round 0.813 hole 0.508: 3(0,0)
D-SUB_15P-HDR-HT
  round 1.473 smd: (-8.91,-2.63) (-7.765,-0.63) (-6.62,-2.63) (5.975,-0.63) (7.12,1.37) (7.12,-2.63)
  round 1.473 hole 1.067: 1(-4.33,-2.63) 2(-2.04,-2.63) 3(0.25,-2.63) 4(2.54,-2.63) 5(4.83,-2.63) 6(-5.475,-0.63) 7(-3.185,-0.63) 8(-0.895,-0.63) 9(1.395,-0.63) 10(3.685,-0.63) 11(-4.33,1.37) 12(-2.04,1.37) 13(0.25,1.37) 14(2.54,1.37) 15(4.83,1.37)
  round 3.607 hole 3.251: 16(-12.495,-0.63) 17(12.495,-0.63)
DDR3_240P_2
  round 2.464 hole 2.464 unplated: (0.95,7.5) (0.95,-130.5)
  oval 2.438x1.829 hole 2.438x1.829 unplated: (0.95,-49.5)
  rect 1.016x1.016 hole 0.711: 1(0,0)
  round 1.016 hole 0.711: 2(-1.9,-1) 3(0,-2) 4(-1.9,-3) 5(0,-4) 6(-1.9,-5) 7(0,-6) 8(-1.9,-7) 9(0,-8) 10(-1.9,-9) 11(0,-10) 12(-1.9,-11) 13(0,-12) 14(-1.9,-13) 15(0,-14) 16(-1.9,-15) 17(0,-16) 18(-1.9,-17) 19(0,-18) 20(-1.9,-19) 21(0,-20) 22(-1.9,-21) 23(0,-22) 24(-1.9,-23) 25(0,-24) 26(-1.9,-25) 27(0,-26) 28(-1.9,-27) 29(0,-28) 30(-1.9,-29) 31(0,-30) 32(-1.9,-31) 33(0,-32) 34(-1.9,-33) 35(0,-34) 36(-1.9,-35) 37(0,-36) 38(-1.9,-37) 39(0,-38) 40(-1.9,-39) 41(0,-40) 42(-1.9,-41) 43(0,-42) 44(-1.9,-43) 45(0,-44) 46(-1.9,-45) 47(0,-46) 48(-1.9,-47) 49(0,-52) 50(-1.9,-53) 51(0,-54) 52(-1.9,-55) 53(0,-56) 54(-1.9,-57) 55(0,-58) 56(-1.9,-59) 57(0,-60) 58(-1.9,-61) 59(0,-62) 60(-1.9,-63) 61(0,-64) 62(-1.9,-65) 63(0,-66) 64(-1.9,-67) 65(0,-68) 66(-1.9,-69) 67(0,-70) 68(-1.9,-71) 69(0,-72) 70(-1.9,-73) 71(0,-74) 72(-1.9,-75) 73(0,-76) 74(-1.9,-77) 75(0,-78) 76(-1.9,-79) 77(0,-80) 78(-1.9,-81) 79(0,-82) 80(-1.9,-83) 81(0,-84) 82(-1.9,-85) 83(0,-86) 84(-1.9,-87) 85(0,-88) 86(-1.9,-89) 87(0,-90) 88(-1.9,-91) 89(0,-92) 90(-1.9,-93) 91(0,-94) 92(-1.9,-95) 93(0,-96) 94(-1.9,-97) 95(0,-98) 96(-1.9,-99) 97(0,-100) 98(-1.9,-101) 99(0,-102) 100(-1.9,-103) 101(0,-104) 102(-1.9,-105) 103(0,-106) 104(-1.9,-107) 105(0,-108) 106(-1.9,-109) 107(0,-110) 108(-1.9,-111) 109(0,-112) 110(-1.9,-113) 111(0,-114) 112(-1.9,-115) 113(0,-116) 114(-1.9,-117) 115(0,-118) 116(-1.9,-119) 117(0,-120) 118(-1.9,-121) 119(0,-122) 120(-1.9,-123) 121(3.8,0) 122(1.9,-1) 123(3.8,-2) 124(1.9,-3) 125(3.8,-4) 126(1.9,-5) 127(3.8,-6) 128(1.9,-7) 129(3.8,-8) 130(1.9,-9) 131(3.8,-10) 132(1.9,-11) 133(3.8,-12) 134(1.9,-13) 135(3.8,-14) 136(1.9,-15) 137(3.8,-16) 138(1.9,-17) 139(3.8,-18) 140(1.9,-19) 141(3.8,-20) 142(1.9,-21) 143(3.8,-22) 144(1.9,-23) 145(3.8,-24) 146(1.9,-25) 147(3.8,-26) 148(1.9,-27) 149(3.8,-28) 150(1.9,-29) 151(3.8,-30) 152(1.9,-31) 153(3.8,-32) 154(1.9,-33) 155(3.8,-34) 156(1.9,-35) 157(3.8,-36) 158(1.9,-37) 159(3.8,-38) 160(1.9,-39) 161(3.8,-40) 162(1.9,-41) 163(3.8,-42) 164(1.9,-43) 165(3.8,-44) 166(1.9,-45) 167(3.8,-46) 168(1.9,-47) 169(3.8,-52) 170(1.9,-53) 171(3.8,-54) 172(1.9,-55) 173(3.8,-56) 174(1.9,-57) 175(3.8,-58) 176(1.9,-59) 177(3.8,-60) 178(1.9,-61) 179(3.8,-62) 180(1.9,-63) 181(3.8,-64) 182(1.9,-65) 183(3.8,-66) 184(1.9,-67) 185(3.8,-68) 186(1.9,-69) 187(3.8,-70) 188(1.9,-71) 189(3.8,-72) 190(1.9,-73) 191(3.8,-74) 192(1.9,-75) 193(3.8,-76) 194(1.9,-77) 195(3.8,-78) 196(1.9,-79) 197(3.8,-80) 198(1.9,-81) 199(3.8,-82) 200(1.9,-83) 201(3.8,-84) 202(1.9,-85) 203(3.8,-86) 204(1.9,-87) 205(3.8,-88) 206(1.9,-89) 207(3.8,-90) 208(1.9,-91) 209(3.8,-92) 210(1.9,-93) 211(3.8,-94) 212(1.9,-95) 213(3.8,-96) 214(1.9,-97) 215(3.8,-98) 216(1.9,-99) 217(3.8,-100) 218(1.9,-101) 219(3.8,-102) 220(1.9,-103) 221(3.8,-104) 222(1.9,-105) 223(3.8,-106) 224(1.9,-107) 225(3.8,-108) 226(1.9,-109) 227(3.8,-110) 228(1.9,-111) 229(3.8,-112) 230(1.9,-113) 231(3.8,-114) 232(1.9,-115) 233(3.8,-116) 234(1.9,-117) 235(3.8,-118) 236(1.9,-119) 237(3.8,-120) 238(1.9,-121) 239(3.8,-122) 240(1.9,-123)
DFN6_PT065_SM2203NSQG
  rect 0.406x0.508 smd: 1(-0.65,-0.967) 2(0,-0.967) 3(0.65,-0.967) 4(0.65,0.967) 5(0,0.967) 6(-0.65,0.967)
  rect 1.016x1.016 smd: 7(-0.27,0)
  rect 0.305x0.762 smd: 8(0.59,0.03)
DFN8_NCP5359A_1
  rect 0.305x0.635 smd: 1(-0.75,-0.925) 2(-0.25,-0.925) 3(0.25,-0.925) 4(0.75,-0.925) 5(0.75,0.925) 6(0.25,0.925) 7(-0.25,0.925) 8(-0.75,0.925)
  rect 1.2x0.8 smd: 9(0,0)
DFN8_PT05_ISL6208_1
  oval 0.279x0.559 smd: 1(-0.75,-0.95) 2(-0.25,-0.95) 3(0.25,-0.95) 4(0.75,-0.95) 5(0.75,0.95) 6(0.25,0.95) 7(-0.25,0.95) 8(-0.75,0.95)
  rect 1.55x0.9 smd: 9(0,0)
DFN10_PT05_RT8015A_1
  rect 0.305x0.762 smd: 1(-1,-1.4) 2(-0.5,-1.4) 3(0,-1.4) 4(0.5,-1.4) 5(1,-1.4) 6(1,1.4) 7(0.5,1.4) 8(0,1.4) 9(-0.5,1.4) 10(-1,1.4)
  rect 2.475x1.625 smd: 11(0,0)
EC2D5_6D3_H8MM
  round 1.372 hole 1.016: 1(-1.25,0) 2(1.25,0)
EC2D5_6D3_H9MM
  round 1.372 hole 1.016: 1(-1.25,0) 2(1.25,0)
EC2D5_6D3_H11MM
  round 1.372 hole 1.016: 1(-1.25,0) 2(1.25,0)
EC2D5_6D3_H12D5MM
  round 1.372 hole 1.016: 1(-1.25,0) 2(1.25,0)
EC3D5_8_H11D5MM_1P
  round 1.676 hole 1.219: 1(-1.75,0)
  round 1.372 hole 1.016: 2(1.75,0)
EC3D5_8_H11MM_1P
  round 1.676 hole 1.219: 1(-1.75,0)
  round 1.372 hole 1.016: 2(1.75,0)
EC200_260_SMD
  rect 3.454x1.524 smd: 1(2.5,0) 2(-2.5,0)
ETXTALS-SPAD_1
  round 1.016 hole 0.66: 1(-6.35,-1.27) 2(-6.35,1.27)
  round 1.27 hole 0.813: 3(0,-2.54) 4(0,2.54)
FB0402_2
  oval 0.572x0.508 smd: 1(-0.476,0) 2(0.476,0)
FB0603_2
  oval 0.889x0.762 smd: 1(-0.699,0) 2(0.699,0)
FB0805_2
  oval 1.143x1.397 smd: 1(-0.953,0) 2(0.953,0)
FCQFN16_RT7290A_NB669
  oval 1.295x0.254 smd: 1(-1.3,0.525) 2(-1.3,-0.175) 8(1.3,-0.525) 9(1.3,0.175)
  oval 0.203x0.813 smd: 3(-0.8,-1.4) 4(-0.4,-1.4) 5(0,-1.4) 6(0.4,-1.4) 7(0.8,-1.4) 10(0.8,1.4) 11(0.4,1.4) 12(0,1.4) 13(-0.4,1.4) 14(-0.8,1.4)
  rect 0.675x0.2 smd: 15(0,0.165) 16(0,-0.435)
FPC_4P10_R_1
  rect 0.2x0.675 smd: 1(-1,-0.437) 2(-0.5,-0.437) 4(0.5,-0.437) 5(1,-0.437) 6(1,0.437) 7(0.5,0.437) 9(-0.5,0.437) 10(-1,0.437)
  rect 0.4x1.55 smd: 8(0,0)
FUSE_SMD_1
  rect 1.905x3.404 smd: 1(-2.223,0) 2(2.223,0)
HDMI_19P-F_SMD-HIGH-TOP_5
  rect 0.279x2.997 smd: 1(4.5,5.077) 2(4,5.077) 3(3.5,5.077) 4(3,5.077) 5(2.5,5.077) 6(2,5.077) 7(1.5,5.077) 8(1,5.077) 9(0.5,5.077) 10(0,5.077) 11(-0.5,5.077) 12(-1,5.077) 13(-1.5,5.077) 14(-2,5.077) 15(-2.5,5.077) 16(-3,5.077) 17(-3.5,5.077) 18(-4,5.077) 19(-4.5,5.077)
  oval 1.524x3.353 hole 0.914x2.743: 20(7.25,4.142) 21(-7.25,4.142)
  oval 1.524x2.235 hole 0.914x1.626: 22(7.25,-1.818) 23(-7.25,-1.818)
HOLE8_5
  round 4.064 hole 4.064 unplated: (0,0)
  round 0.66 hole 0.356: 1(0,3.992) 2(-2.823,2.823) 3(-3.992,0) 4(-2.823,-2.823) 5(0,-3.992) 6(2.823,-2.823) 7(3.992,0) 8(2.823,2.823)
HOLE_TC256BC180D165PT
  round 6.502 hole 4.191: 1(0,0)
J2X1
  rect 1.372x1.372 hole 1.016: 1(-1.27,0)
  round 1.372 hole 1.016: 2(1.27,0)
J3X1
  rect 1.372x1.372 hole 1.016: 1(-2.54,0)
  round 1.372 hole 1.016: 2(0,0) 3(2.54,0)
J3X2
  rect 1.372x1.372 hole 1.016: 1(-2.54,-1.27)
  round 1.372 hole 1.016: 2(-2.54,1.27) 3(0,-1.27) 4(0,1.27) 5(2.54,-1.27) 6(2.54,1.27)
J4X1_PT2D5MM-LONGSHOUNG_1
  rect 1.422x1.422 hole 1.016: 1(3.75,-0.45)
  round 1.422 hole 1.016: 2(1.25,-0.45) 3(-1.25,-0.45) 4(-3.75,-0.45)
J4X1_WAFER
  rect 1.372x1.372 hole 1.016: 1(3.81,0)
  round 1.372 hole 1.016: 2(1.27,0) 3(-1.27,0) 4(-3.81,0)
J5X1_CR
  rect 1.372x1.372 hole 1.016: 1(-5.08,0)
  round 1.372 hole 1.016: 2(-2.54,0) 3(0,0) 4(2.54,0)
J5X2_AUDIO_1
  rect 1.372x1.372 hole 1.016: 1(-5.08,-1.27)
  round 1.372 hole 1.016: 2(-5.08,1.27) 3(-2.54,-1.27) 4(-2.54,1.27) 5(0,-1.27) 6(0,1.27) 7(2.54,-1.27) 9(5.08,-1.27) 10(5.08,1.27)
J5X2_PT1D27MM_SMD_2P_1
  rect 0.711x2.616 smd: 1(-2.54,-1.712) 3(-1.27,-1.712) 4(-1.27,1.712) 5(0,-1.712) 6(0,1.712) 7(1.27,-1.712) 8(1.27,1.712) 9(2.54,-1.712) 10(2.54,1.712)
J5X2_USB_1394
  rect 1.372x1.372 hole 1.016: 1(-5.08,-1.27)
  round 1.372 hole 1.016: 2(-5.08,1.27) 3(-2.54,-1.27) 4(-2.54,1.27) 5(0,-1.27) 6(0,1.27) 7(2.54,-1.27) 8(2.54,1.27) 10(5.08,1.27)
J7X2_PANEL_10P
  rect 1.372x1.372 hole 1.016: 1(-7.62,-1.27)
  round 1.372 hole 1.016: 2(-7.62,1.27) 3(-5.08,-1.27) 4(-5.08,1.27) 5(-2.54,-1.27) 6(-2.54,1.27) 7(0,-1.27) 8(0,1.27) 9(2.54,-1.27) 11(5.08,-1.27) 12(5.08,1.27) 13(7.62,-1.27) 14(7.62,1.27)
J10X2_JLPC
  rect 1.372x1.372 hole 1.016: 1(-11.43,-1.27)
  round 1.372 hole 1.016: 2(-11.43,1.27) 3(-8.89,-1.27) 5(-6.35,-1.27) 6(-6.35,1.27) 7(-3.81,-1.27) 8(-3.81,1.27) 9(-1.27,-1.27) 10(-1.27,1.27) 11(1.27,-1.27) 12(1.27,1.27) 13(3.81,-1.27) 14(3.81,1.27) 15(6.35,-1.27) 16(6.35,1.27) 17(8.89,-1.27) 18(8.89,1.27) 19(11.43,-1.27) 20(11.43,1.27)
JOPEN_200X60
  rect 5.08x1.524 smd: 1(0,-0.914) 2(0,0.914)
JOPEN_200X60-NMNP
  rect 5.08x1.676 smd: 1(0,-0.838) 2(0,0.838)
L0805_2
  oval 1.016x1.397 smd: 1(-0.889,0) 2(0.889,0)
LGA1151-INTEL
  round 4.064 hole 4.064 unplated: (-38.12,37.5) (-38.12,-37.5) (36.89,37.5) (36.89,-37.5)
  round 3.861 hole 3.861 unplated: (-35.21,0) (25.81,18) (25.81,-18)
  round 1.016 smd: (-19.558,-19.558) (19.812,19.812)
  round 0.66 hole 0.356: 1(-38.12,41) 2(-41.62,37.5) 3(-38.12,34) 4(-34.62,37.5) 5(36.89,41) 6(33.39,37.5) 7(36.89,34) 8(40.39,37.5) 9(-38.12,-34) 10(-41.62,-37.5) 11(-38.12,-41) 12(-34.62,-37.5) 13(36.89,-34) 14(33.39,-37.5) 15(36.89,-41) 16(40.39,-37.5)
  round 0.508 smd: A4(-16.187,18.288) A5(-15.273,18.288) AT40(18.931,-14.63) AU1(-18.931,-14.63) AU39(18.016,-15.545) AU40(18.931,-15.545) AV1(-18.931,-15.545) AV2(-18.016,-15.545) AV38(17.102,-16.459) AV39(18.016,-16.459) AW2(-18.016,-16.459) AW3(-17.102,-16.459) AW37(16.187,-17.374) AW38(17.102,-17.374) AY3(-17.102,-17.374) AY4(-16.187,-17.374) B3(-17.102,17.374) B4(-16.187,17.374) B37(16.187,16.459) B38(17.102,16.459) B39(18.016,16.459) C2(-18.016,16.459) C3(-17.102,16.459) C39(18.016,15.545) C40(18.931,15.545) D1(-18.931,15.545) D2(-18.016,15.545) D40(18.931,14.63) E40(18.931,13.716)
  round 0.429 smd: A6(-14.359,18.288) A7(-13.444,18.288) A25(3.015,18.288) A26(3.929,18.288) A27(4.844,18.288) A28(5.758,18.288) A29(6.673,18.288) A30(7.587,18.288) AA5(-15.273,0) AA6(-14.359,0) AA7(-13.444,0) AA8(-12.53,0) AA33(12.53,-0.914) AA34(13.444,-0.914) AA35(14.359,-0.914) AA36(15.273,-0.914) AA37(16.187,-0.914) AA38(17.102,-0.914) AB5(-15.273,-0.914) AB6(-14.359,-0.914) AB7(-13.444,-0.914) AB8(-12.53,-0.914) AB33(12.53,-1.829) AB34(13.444,-1.829) AB35(14.359,-1.829) AB36(15.273,-1.829) AB37(16.187,-1.829) AC5(-15.273,-1.829) AC6(-14.359,-1.829) AC7(-13.444,-1.829) AC8(-12.53,-1.829) AC33(12.53,-2.743) AC34(13.444,-2.743) AC35(14.359,-2.743) AC36(15.273,-2.743) AC37(16.187,-2.743) AD3(-17.102,-2.743) AD4(-16.187,-2.743) AD5(-15.273,-2.743) AD6(-14.359,-2.743) AD7(-13.444,-2.743) AD8(-12.53,-2.743) AD33(12.53,-3.658) AD34(13.444,-3.658) AD35(14.359,-3.658) AD36(15.273,-3.658) AD37(16.187,-3.658) AE3(-17.102,-3.658) AE4(-16.187,-3.658) AE5(-15.273,-3.658) AE6(-14.359,-3.658) AE7(-13.444,-3.658) AE8(-12.53,-3.658) AE33(12.53,-4.572) AE34(13.444,-4.572) AE35(14.359,-4.572) AE36(15.273,-4.572) AE37(16.187,-4.572) AE38(17.102,-4.572) AF4(-16.187,-4.572) AF5(-15.273,-4.572) AF6(-14.359,-4.572) AF7(-13.444,-4.572) AF8(-12.53,-4.572) AF33(12.53,-5.486) AF34(13.444,-5.486) AF35(14.359,-5.486) AF36(15.273,-5.486) AF37(16.187,-5.486) AF38(17.102,-5.486) AG4(-16.187,-5.486) AG5(-15.273,-5.486) AG6(-14.359,-5.486) AG7(-13.444,-5.486) AG8(-12.53,-5.486) AG33(12.53,-6.401) AG34(13.444,-6.401) AG35(14.359,-6.401) AG36(15.273,-6.401) AG37(16.187,-6.401) AG38(17.102,-6.401) AH3(-17.102,-6.401) AH4(-16.187,-6.401) AH5(-15.273,-6.401) AH6(-14.359,-6.401) AH7(-13.444,-6.401) AH8(-12.53,-6.401) AH33(12.53,-7.315) AH34(13.444,-7.315) AH35(14.359,-7.315) AH36(15.273,-7.315) AH37(16.187,-7.315) AH38(17.102,-7.315) AJ3(-17.102,-7.315) AJ4(-16.187,-7.315) AJ5(-15.273,-7.315) AJ6(-14.359,-7.315) AJ7(-13.444,-7.315) AJ8(-12.53,-7.315) AJ9(-11.615,-7.315) AJ11(-7.587,-8.23) AJ12(-6.673,-8.23) AJ13(-5.758,-8.23) AJ14(-4.844,-8.23) AJ15(-3.929,-8.23) AJ16(-3.015,-8.23) AJ17(-2.101,-8.23) AJ18(-1.186,-8.23) AJ19(-0.272,-8.23) AJ20(0.643,-8.23) AJ21(1.557,-8.23) AJ22(2.471,-8.23) AJ23(3.386,-8.23) AJ24(4.3,-8.23) AJ25(5.215,-8.23) AJ26(6.129,-8.23) AJ27(7.043,-8.23) AJ28(7.958,-8.23) AJ29(8.872,-8.23) AJ30(9.787,-8.23) AJ31(10.701,-8.23) AJ32(11.615,-8.23) AJ33(12.53,-8.23) AJ34(13.444,-8.23) AJ35(14.359,-8.23) AJ36(15.273,-8.23) AJ37(16.187,-8.23) AJ38(17.102,-8.23) AK3(-17.102,-8.23) AK4(-16.187,-8.23) AK5(-15.273,-8.23) AK6(-14.359,-8.23) AK7(-13.444,-8.23) AK8(-12.53,-8.23) AK9(-11.615,-8.23) AK10(-10.701,-8.23) AK11(-7.587,-9.144) AK12(-6.673,-9.144) AK13(-5.758,-9.144) AK14(-4.844,-9.144) AK15(-3.929,-9.144) AK16(-3.015,-9.144) AK17(-2.101,-9.144) AK18(-1.186,-9.144) AK19(-0.272,-9.144) AK20(0.643,-9.144) AK21(1.557,-9.144) AK22(2.471,-9.144) AK23(3.386,-9.144) AK24(4.3,-9.144) AK25(5.215,-9.144) AK26(6.129,-9.144) AK27(7.043,-9.144) AK28(7.958,-9.144) AK29(8.872,-9.144) AK30(9.787,-9.144) AK31(10.701,-9.144) AK32(11.615,-9.144) AK33(12.53,-9.144) AK34(13.444,-9.144) AK35(14.359,-9.144) AK36(15.273,-9.144) AK37(16.187,-9.144) AK38(17.102,-9.144) AL3(-17.102,-9.144) AL4(-16.187,-9.144) AL5(-15.273,-9.144) AL6(-14.359,-9.144) AL7(-13.444,-9.144) AL8(-12.53,-9.144) AL9(-11.615,-9.144) AL10(-10.701,-9.144) AL11(-7.587,-10.058) AL12(-6.673,-10.058) AL13(-5.758,-10.058) AL14(-4.844,-10.058) AL15(-3.929,-10.058) AL16(-3.015,-10.058) AL17(-2.101,-10.058) AL18(-1.186,-10.058) AL19(-0.272,-10.058) AL20(0.643,-10.058) AL21(1.557,-10.058) AL22(2.471,-10.058) AL23(3.386,-10.058) AL24(4.3,-10.058) AL25(5.215,-10.058) AL26(6.129,-10.058) AL27(7.043,-10.058) AL28(7.958,-10.058) AL29(8.872,-10.058) AL30(9.787,-10.058) AL31(10.701,-10.058) AL32(11.615,-10.058) AL33(12.53,-10.058) AL34(13.444,-10.058) AL35(14.359,-10.058) AL36(15.273,-10.058) AL37(16.187,-10.058) AL38(17.102,-10.058) AM3(-17.102,-10.058) AM4(-16.187,-10.058) AM5(-15.273,-10.058) AM6(-14.359,-10.058) AM7(-13.444,-10.058) AM8(-12.53,-10.058) AM9(-11.615,-10.058) AM10(-10.701,-10.058) AM11(-7.587,-10.973) AM12(-6.673,-10.973) AM13(-5.758,-10.973) AM14(-4.844,-10.973) AM15(-3.929,-10.973) AM16(-3.015,-10.973) AM17(-2.101,-10.973) AM18(-1.186,-10.973) AM19(-0.272,-10.973) AM20(0.643,-10.973) AM21(1.557,-10.973) AM22(2.471,-10.973) AM23(3.386,-10.973) AM24(4.3,-10.973) AM25(5.215,-10.973) AM26(6.129,-10.973) AM27(7.043,-10.973) AM28(7.958,-10.973) AM29(8.872,-10.973) AM30(9.787,-10.973) AM31(10.701,-10.973) AM32(11.615,-10.973) AM33(12.53,-10.973) AM34(13.444,-10.973) AM35(14.359,-10.973) AM36(15.273,-10.973) AM37(16.187,-10.973) AM38(17.102,-10.973) AN3(-17.102,-10.973) AN4(-16.187,-10.973) AN5(-15.273,-10.973) AN6(-14.359,-10.973) AN7(-13.444,-10.973) AN8(-12.53,-10.973) AN9(-11.615,-10.973) AN10(-10.701,-10.973) AN11(-7.587,-11.887) AN12(-6.673,-11.887) AN13(-5.758,-11.887) AN14(-4.844,-11.887) AN15(-3.929,-11.887) AN16(-3.015,-11.887) AN17(-2.101,-11.887) AN18(-1.186,-11.887) AN19(-0.272,-11.887) AN20(0.643,-11.887) AN21(1.557,-11.887) AN22(2.471,-11.887) AN23(3.386,-11.887) AN24(4.3,-11.887) AN25(5.215,-11.887) AN26(6.129,-11.887) AN27(7.043,-11.887) AN28(7.958,-11.887) AN29(8.872,-11.887) AN30(9.787,-11.887) AN31(10.701,-11.887) AN32(11.615,-11.887) AN33(12.53,-11.887) AN34(13.444,-11.887) AN35(14.359,-11.887) AN36(15.273,-11.887) AN37(16.187,-11.887) AN38(17.102,-11.887) AP3(-17.102,-11.887) AP4(-16.187,-11.887) AP5(-15.273,-11.887) AP6(-14.359,-11.887) AP7(-13.444,-11.887) AP8(-12.53,-11.887) AP9(-11.615,-11.887) AP10(-10.701,-11.887) AP11(-7.587,-12.802) AP12(-6.673,-12.802) AP13(-5.758,-12.802) AP14(-4.844,-12.802) AP15(-3.929,-12.802) AP16(-3.015,-12.802) AP17(-2.101,-12.802) AP18(-1.186,-12.802) AP19(-0.272,-12.802) AP20(0.643,-12.802) AP21(1.557,-12.802) AP22(2.471,-12.802) AP23(3.386,-12.802) AP24(4.3,-12.802) AP25(5.215,-12.802) AP26(6.129,-12.802) AP27(7.043,-12.802) AP28(7.958,-12.802) AP29(8.872,-12.802) AP30(9.787,-12.802) AP31(10.701,-12.802) AP32(11.615,-12.802) AP33(12.53,-12.802) AP34(13.444,-12.802) AP35(14.359,-12.802) AP36(15.273,-12.802) AP37(16.187,-12.802) AP38(17.102,-12.802) AR3(-17.102,-12.802) AR4(-16.187,-12.802) AR5(-15.273,-12.802) AR6(-14.359,-12.802) AR7(-13.444,-12.802) AR8(-12.53,-12.802) AR9(-11.615,-12.802) AR10(-10.701,-12.802) AR11(-7.587,-13.716) AR12(-6.673,-13.716) AR13(-5.758,-13.716) AR14(-4.844,-13.716) AR15(-3.929,-13.716) AR16(-3.015,-13.716) AR17(-2.101,-13.716) AR18(-1.186,-13.716) AR19(-0.272,-13.716) AR20(0.643,-13.716) AR21(1.557,-13.716) AR22(2.471,-13.716) AR23(3.386,-13.716) AR24(4.3,-13.716) AR25(5.215,-13.716) AR26(6.129,-13.716) AR27(7.043,-13.716) AR28(7.958,-13.716) AR29(8.872,-13.716) AR30(9.787,-13.716) AR31(10.701,-13.716) AR32(11.615,-13.716) AR33(12.53,-13.716) AR34(13.444,-13.716) AR35(14.359,-13.716) AR36(15.273,-13.716) AR37(16.187,-13.716) AR38(17.102,-13.716) AT3(-17.102,-13.716) AT4(-16.187,-13.716) AT5(-15.273,-13.716) AT6(-14.359,-13.716) AT7(-13.444,-13.716) AT8(-12.53,-13.716) AT9(-11.615,-13.716) AT10(-10.701,-13.716) AT11(-7.587,-14.63) AT12(-6.673,-14.63) AT13(-5.758,-14.63) AT14(-4.844,-14.63) AT15(-3.929,-14.63) AT16(-3.015,-14.63) AT17(-2.101,-14.63) AT18(-1.186,-14.63) AT19(-0.272,-14.63) AT20(0.643,-14.63) AT21(1.557,-14.63) AT22(2.471,-14.63) AT23(3.386,-14.63) AT24(4.3,-14.63) AT25(5.215,-14.63) AT26(6.129,-14.63) AT27(7.043,-14.63) AT28(7.958,-14.63) AT29(8.872,-14.63) AT30(9.787,-14.63) AT31(10.701,-14.63) AT32(11.615,-14.63) AT33(12.53,-14.63) AT34(13.444,-14.63) AT35(14.359,-14.63) AT36(15.273,-14.63) AT37(16.187,-14.63) AT38(17.102,-14.63) AU3(-17.102,-14.63) AU4(-16.187,-14.63) AU5(-15.273,-14.63) AU6(-14.359,-14.63) AU7(-13.444,-14.63) AU8(-12.53,-14.63) AU9(-11.615,-14.63) AU10(-10.701,-14.63) AU11(-7.587,-15.545) AU12(-6.673,-15.545) AU13(-5.758,-15.545) AU14(-4.844,-15.545) AU15(-3.929,-15.545) AU16(-3.015,-15.545) AU17(-2.101,-15.545) AU18(-1.186,-15.545) AU19(-0.272,-15.545) AU20(0.643,-15.545) AU21(1.557,-15.545) AU24(4.3,-15.545) AU25(5.215,-15.545) AU26(6.129,-15.545) AU27(7.043,-15.545) AU28(7.958,-15.545) AU29(8.872,-15.545) AU30(9.787,-15.545) AU31(10.701,-15.545) AU32(11.615,-15.545) AU33(12.53,-15.545) AU34(13.444,-15.545) AU35(14.359,-15.545) AU36(15.273,-15.545) AU37(16.187,-15.545) AU38(17.102,-15.545) AV3(-17.102,-15.545) AV4(-16.187,-15.545) AV5(-15.273,-15.545) AV6(-14.359,-15.545) AV7(-13.444,-15.545) AV8(-12.53,-15.545) AV9(-11.615,-15.545) AV10(-10.701,-15.545) AV11(-7.587,-16.459) AV12(-6.673,-16.459) AV13(-5.758,-16.459) AV14(-4.844,-16.459) AV24(4.3,-16.459) AV25(5.215,-16.459) AV28(7.958,-16.459) AV29(8.872,-16.459) AV37(16.187,-16.459) AW4(-16.187,-16.459) AW9(-11.615,-16.459) AW10(-10.701,-16.459) AW11(-7.587,-17.374) AW12(-6.673,-17.374) AW13(-5.758,-17.374) AW14(-4.844,-17.374) AY10(-10.701,-17.374) B5(-15.273,17.374) B6(-14.359,17.374) B7(-13.444,17.374) B25(3.015,17.374) B26(3.929,17.374) B27(4.844,17.374) B28(5.758,17.374) B29(6.673,17.374) B30(7.587,17.374) B31(10.701,16.459) B32(11.615,16.459) B33(12.53,16.459) B34(13.444,16.459) B35(14.359,16.459) B36(15.273,16.459) C4(-16.187,16.459) C5(-15.273,16.459) C6(-14.359,16.459) C7(-13.444,16.459) C8(-12.53,16.459) C9(-11.615,16.459) C12(-8.872,16.459) C13(-7.958,16.459) C14(-7.043,16.459) C15(-6.129,16.459) C16(-5.215,16.459) C17(-4.3,16.459) C25(3.015,16.459) C26(3.929,16.459) C27(4.844,16.459) C28(5.758,16.459) C29(6.673,16.459) C30(7.587,16.459) C31(10.701,15.545) C32(11.615,15.545) C33(12.53,15.545) C34(13.444,15.545) C35(14.359,15.545) C36(15.273,15.545) C37(16.187,15.545) C38(17.102,15.545) D3(-17.102,15.545) D4(-16.187,15.545) D5(-15.273,15.545) D6(-14.359,15.545) D7(-13.444,15.545) D8(-12.53,15.545) D9(-11.615,15.545) D10(-10.701,15.545) D11(-9.787,15.545) D12(-8.872,15.545) D13(-7.958,15.545) D14(-7.043,15.545) D15(-6.129,15.545) D16(-5.215,15.545) D17(-4.3,15.545) D24(2.101,15.545) D25(3.015,15.545) D26(3.929,15.545) D27(4.844,15.545) D28(5.758,15.545) D29(6.673,15.545) D30(7.587,15.545) D31(10.701,14.63) D32(11.615,14.63) D33(12.53,14.63) D34(13.444,14.63) D35(14.359,14.63) D36(15.273,14.63) D37(16.187,14.63) D38(17.102,14.63) D39(18.016,14.63) E3(-17.102,14.63) E4(-16.187,14.63) E5(-15.273,14.63) E6(-14.359,14.63) E7(-13.444,14.63) E8(-12.53,14.63) E9(-11.615,14.63) E10(-10.701,14.63) E11(-9.787,14.63) E12(-8.872,14.63) E13(-7.958,14.63) E14(-7.043,14.63) E15(-6.129,14.63) E16(-5.215,14.63) E17(-4.3,14.63) E18(-3.386,14.63) E19(-2.471,14.63) E21(-0.643,14.63) E23(1.186,14.63) E24(2.101,14.63) E25(3.015,14.63) E26(3.929,14.63) E27(4.844,14.63) E28(5.758,14.63) E29(6.673,14.63) E30(7.587,14.63) E31(10.701,13.716) E32(11.615,13.716) E33(12.53,13.716) E34(13.444,13.716) E35(14.359,13.716) E36(15.273,13.716) E37(16.187,13.716) E38(17.102,13.716) E39(18.016,13.716) F4(-16.187,13.716) F5(-15.273,13.716) F6(-14.359,13.716) F7(-13.444,13.716) F8(-12.53,13.716) F9(-11.615,13.716) F10(-10.701,13.716) F11(-9.787,13.716) F12(-8.872,13.716) F13(-7.958,13.716) F14(-7.043,13.716) F15(-6.129,13.716) F16(-5.215,13.716) F17(-4.3,13.716) F18(-3.386,13.716) F19(-2.471,13.716) F20(-1.557,13.716) F21(-0.643,13.716) F22(0.272,13.716) F23(1.186,13.716) F24(2.101,13.716) F25(3.015,13.716) F26(3.929,13.716) F27(4.844,13.716) F28(5.758,13.716) F29(6.673,13.716) F30(7.587,13.716) F31(10.701,12.802) F32(11.615,12.802) F33(12.53,12.802) F34(13.444,12.802) F35(14.359,12.802) F36(15.273,12.802) F37(16.187,12.802) F38(17.102,12.802) F39(18.016,12.802) F40(18.931,12.802) G3(-17.102,12.802) G4(-16.187,12.802) G5(-15.273,12.802) G6(-14.359,12.802) G7(-13.444,12.802) G8(-12.53,12.802) G9(-11.615,12.802) G10(-10.701,12.802) G11(-9.787,12.802) G12(-8.872,12.802) G13(-7.958,12.802) G14(-7.043,12.802) G15(-6.129,12.802) G16(-5.215,12.802) G17(-4.3,12.802) G18(-3.386,12.802) G19(-2.471,12.802) G20(-1.557,12.802) G21(-0.643,12.802) G22(0.272,12.802) G23(1.186,12.802) G24(2.101,12.802) G25(3.015,12.802) G26(3.929,12.802) G27(4.844,12.802) G28(5.758,12.802) G29(6.673,12.802) G30(7.587,12.802) G31(10.701,11.887) G32(11.615,11.887) G33(12.53,11.887) G34(13.444,11.887) G35(14.359,11.887) G36(15.273,11.887) G37(16.187,11.887) G38(17.102,11.887) G39(18.016,11.887) G40(18.931,11.887) H4(-16.187,11.887) H5(-15.273,11.887) H6(-14.359,11.887) H7(-13.444,11.887) H8(-12.53,11.887) H9(-11.615,11.887) H10(-10.701,11.887) H11(-9.787,11.887) H12(-8.872,11.887) H13(-7.958,11.887) H14(-7.043,11.887) H15(-6.129,11.887) H16(-5.215,11.887) H17(-4.3,11.887) H18(-3.386,11.887) H19(-2.471,11.887) H20(-1.557,11.887) H21(-0.643,11.887) H22(0.272,11.887) H23(1.186,11.887) H24(2.101,11.887) H25(3.015,11.887) H26(3.929,11.887) H27(4.844,11.887) H28(5.758,11.887) H29(6.673,11.887) H30(7.587,11.887) H31(10.701,10.973) H32(11.615,10.973) H33(12.53,10.973) H34(13.444,10.973) H35(14.359,10.973) H36(15.273,10.973) H37(16.187,10.973) H38(17.102,10.973) H39(18.016,10.973) H40(18.931,10.973) J3(-17.102,10.973) J4(-16.187,10.973) J5(-15.273,10.973) J6(-14.359,10.973) J7(-13.444,10.973) J8(-12.53,10.973) J9(-11.615,10.973) J10(-10.701,10.973) J11(-9.787,10.973) J12(-8.872,10.973) J13(-7.958,10.973) J14(-7.043,10.973) J15(-6.129,10.973) J16(-5.215,10.973) J17(-4.3,10.973) J18(-3.386,10.973) J19(-2.471,10.973) J20(-1.557,10.973) J21(-0.643,10.973) J22(0.272,10.973) J23(1.186,10.973) J24(2.101,10.973) J25(3.015,10.973) J26(3.929,10.973) J27(4.844,10.973) J28(5.758,10.973) J29(6.673,10.973) J30(7.587,10.973) J31(10.701,10.058) J32(11.615,10.058) J33(12.53,10.058) J34(13.444,10.058) J35(14.359,10.058) J36(15.273,10.058) J37(16.187,10.058) J38(17.102,10.058) J39(18.016,10.058) J40(18.931,10.058) K4(-16.187,10.058) K5(-15.273,10.058) K6(-14.359,10.058) K7(-13.444,10.058) K8(-12.53,10.058) K9(-11.615,10.058) K10(-10.701,10.058) K11(-9.787,10.058) K12(-8.872,10.058) K13(-7.958,10.058) K14(-7.043,10.058) K15(-6.129,10.058) K16(-5.215,10.058) K17(-4.3,10.058) K18(-3.386,10.058) K19(-2.471,10.058) K20(-1.557,10.058) K21(-0.643,10.058) K22(0.272,10.058) K23(1.186,10.058) K24(2.101,10.058) K25(3.015,10.058) K26(3.929,10.058) K27(4.844,10.058) K28(5.758,10.058) K29(6.673,10.058) K30(7.587,10.058) K31(10.701,9.144) K32(11.615,9.144) K33(12.53,9.144) K34(13.444,9.144) K35(14.359,9.144) K36(15.273,9.144) K37(16.187,9.144) K38(17.102,9.144) K39(18.016,9.144) K40(18.931,9.144) L3(-17.102,9.144) L4(-16.187,9.144) L5(-15.273,9.144) L6(-14.359,9.144) L7(-13.444,9.144) L8(-12.53,9.144) L9(-11.615,9.144) L10(-10.701,9.144) L11(-9.787,9.144) L12(-8.872,9.144) L13(-7.958,9.144) L14(-7.043,9.144) L15(-6.129,9.144) L16(-5.215,9.144) L17(-4.3,9.144) L18(-3.386,9.144) L19(-2.471,9.144) L20(-1.557,9.144) L21(-0.643,9.144) L22(0.272,9.144) L23(1.186,9.144) L24(2.101,9.144) L25(3.015,9.144) L26(3.929,9.144) L27(4.844,9.144) L28(5.758,9.144) L29(6.673,9.144) L30(7.587,9.144) L31(10.701,8.23) L32(11.615,8.23) L33(12.53,8.23) L34(13.444,8.23) L35(14.359,8.23) L36(15.273,8.23) L37(16.187,8.23) L38(17.102,8.23) L39(18.016,8.23) L40(18.931,8.23) M4(-16.187,8.23) M5(-15.273,8.23) M6(-14.359,8.23) M7(-13.444,8.23) M8(-12.53,8.23) M9(-11.615,8.23) M10(-10.701,8.23) M11(-9.787,8.23) M12(-8.872,8.23) M13(-7.958,8.23) M14(-7.043,8.23) M15(-6.129,8.23) M16(-5.215,8.23) M17(-4.3,8.23) M18(-3.386,8.23) M19(-2.471,8.23) M20(-1.557,8.23) M21(-0.643,8.23) M22(0.272,8.23) M23(1.186,8.23) M24(2.101,8.23) M25(3.015,8.23) M26(3.929,8.23) M27(4.844,8.23) M28(5.758,8.23) M29(6.673,8.23) M30(7.587,8.23) M32(11.615,7.315) M33(12.53,7.315) M34(13.444,7.315) M35(14.359,7.315) M36(15.273,7.315) M37(16.187,7.315) M38(17.102,7.315) M39(18.016,7.315) M40(18.931,7.315) N3(-17.102,7.315) N4(-16.187,7.315) N5(-15.273,7.315) N6(-14.359,7.315) N7(-13.444,7.315) N8(-12.53,7.315) N33(12.53,6.401) N34(13.444,6.401) N35(14.359,6.401) N36(15.273,6.401) N37(16.187,6.401) N38(17.102,6.401) N39(18.016,6.401) N40(18.931,6.401) P4(-16.187,6.401) P5(-15.273,6.401) P6(-14.359,6.401) P7(-13.444,6.401) P8(-12.53,6.401) P33(12.53,5.486) P34(13.444,5.486) P35(14.359,5.486) P36(15.273,5.486) P37(16.187,5.486) P38(17.102,5.486) P39(18.016,5.486) P40(18.931,5.486) R3(-17.102,5.486) R4(-16.187,5.486) R5(-15.273,5.486) R6(-14.359,5.486) R7(-13.444,5.486) R8(-12.53,5.486) R33(12.53,4.572) R34(13.444,4.572) R35(14.359,4.572) R36(15.273,4.572) R37(16.187,4.572) R38(17.102,4.572) R39(18.016,4.572) R40(18.931,4.572) T4(-16.187,4.572) T5(-15.273,4.572) T6(-14.359,4.572) T7(-13.444,4.572) T8(-12.53,4.572) T33(12.53,3.658) T34(13.444,3.658) T35(14.359,3.658) T36(15.273,3.658) T37(16.187,3.658) T38(17.102,3.658) T39(18.016,3.658) T40(18.931,3.658) U4(-16.187,3.658) U5(-15.273,3.658) U6(-14.359,3.658) U7(-13.444,3.658) U8(-12.53,3.658) U33(12.53,2.743) U34(13.444,2.743) U35(14.359,2.743) U36(15.273,2.743) U37(16.187,2.743) U38(17.102,2.743) U39(18.016,2.743) U40(18.931,2.743) V4(-16.187,2.743) V5(-15.273,2.743) V6(-14.359,2.743) V7(-13.444,2.743) V8(-12.53,2.743) V33(12.53,1.829) V34(13.444,1.829) V35(14.359,1.829) V36(15.273,1.829) V37(16.187,1.829) V38(17.102,1.829) V39(18.016,1.829) V40(18.931,1.829) W4(-16.187,1.829) W5(-15.273,1.829) W6(-14.359,1.829) W7(-13.444,1.829) W8(-12.53,1.829) W33(12.53,0.914) W34(13.444,0.914) W35(14.359,0.914) W36(15.273,0.914) W37(16.187,0.914) W38(17.102,0.914) Y5(-15.273,0.914) Y6(-14.359,0.914) Y7(-13.444,0.914) Y8(-12.53,0.914) Y33(12.53,0) Y34(13.444,0) Y35(14.359,0) Y36(15.273,0) Y37(16.187,0) Y38(17.102,0)
  oval 0.356x0.457 smd: A11(-9.787,18.288) A12(-8.872,18.288) A13(-7.958,18.288) A14(-7.043,18.288) A15(-6.129,18.288) A16(-5.215,18.288) A17(-4.3,18.288) A18(-3.386,18.288) A23(1.186,18.288) A24(2.101,18.288) AU22(2.471,-15.545) AU23(3.386,-15.545) AV15(-3.929,-16.459) AV16(-3.015,-16.459) AV17(-2.101,-16.459) AV18(-1.186,-16.459) AV19(-0.272,-16.459) AV20(0.643,-16.459) AV21(1.557,-16.459) AV22(2.471,-16.459) AV23(3.386,-16.459) AV26(6.129,-16.459) AV27(7.043,-16.459) AV30(9.787,-16.459) AV31(10.701,-16.459) AV32(11.615,-16.459) AV33(12.53,-16.459) AV34(13.444,-16.459) AV35(14.359,-16.459) AV36(15.273,-16.459) AW5(-15.273,-16.459) AW6(-14.359,-16.459) AW7(-13.444,-16.459) AW8(-12.53,-16.459) AW15(-3.929,-17.374) AW16(-3.015,-17.374) AW17(-2.101,-17.374) AW18(-1.186,-17.374) AW23(3.386,-17.374) AW24(4.3,-17.374) AW25(5.215,-17.374) AW26(6.129,-17.374) AW27(7.043,-17.374) AW28(7.958,-17.374) AW29(8.872,-17.374) AW30(9.787,-17.374) AW31(10.701,-17.374) AW32(11.615,-17.374) AW33(12.53,-17.374) AW34(13.444,-17.374) AW35(14.359,-17.374) AW36(15.273,-17.374) AY5(-15.273,-17.374) AY6(-14.359,-17.374) AY7(-13.444,-17.374) AY8(-12.53,-17.374) AY9(-11.615,-17.374) AY11(-7.587,-18.288) AY12(-6.673,-18.288) AY13(-5.758,-18.288) AY14(-4.844,-18.288) AY15(-3.929,-18.288) AY16(-3.015,-18.288) AY17(-2.101,-18.288) AY18(-1.186,-18.288) AY23(3.386,-18.288) AY24(4.3,-18.288) AY25(5.215,-18.288) AY26(6.129,-18.288) AY27(7.043,-18.288) AY28(7.958,-18.288) AY29(8.872,-18.288) AY30(9.787,-18.288) AY31(10.701,-18.288) B8(-12.53,17.374) B9(-11.615,17.374) B10(-10.701,17.374) B11(-9.787,17.374) B12(-8.872,17.374) B13(-7.958,17.374) B14(-7.043,17.374) B15(-6.129,17.374) B16(-5.215,17.374) B17(-4.3,17.374) B18(-3.386,17.374) B23(1.186,17.374) B24(2.101,17.374) C10(-10.701,16.459) C11(-9.787,16.459) C18(-3.386,16.459) C19(-2.471,16.459) C20(-1.557,16.459) C21(-0.643,16.459) C22(0.272,16.459) C23(1.186,16.459) C24(2.101,16.459) D18(-3.386,15.545) D19(-2.471,15.545) D20(-1.557,15.545) D21(-0.643,15.545) D22(0.272,15.545) D23(1.186,15.545) E20(-1.557,14.63) E22(0.272,14.63)
  oval 0.457x0.356 smd: AA3(-17.102,0) AA4(-16.187,0) AB3(-17.102,-0.914) AB4(-16.187,-0.914) AB38(17.102,-1.829) AB39(18.016,-1.829) AB40(18.931,-1.829) AC1(-18.931,-1.829) AC2(-18.016,-1.829) AC3(-17.102,-1.829) AC4(-16.187,-1.829) AC38(17.102,-2.743) AC39(18.016,-2.743) AC40(18.931,-2.743) AD1(-18.931,-2.743) AD2(-18.016,-2.743) AD38(17.102,-3.658) AD39(18.016,-3.658) AD40(18.931,-3.658) AE1(-18.931,-3.658) AE2(-18.016,-3.658) AE39(18.016,-4.572) AE40(18.931,-4.572) AF1(-18.931,-4.572) AF2(-18.016,-4.572) AF3(-17.102,-4.572) AF39(18.016,-5.486) AF40(18.931,-5.486) AG1(-18.931,-5.486) AG2(-18.016,-5.486) AG3(-17.102,-5.486) AG39(18.016,-6.401) AG40(18.931,-6.401) AH1(-18.931,-6.401) AH2(-18.016,-6.401) AH39(18.016,-7.315) AH40(18.931,-7.315) AJ1(-18.931,-7.315) AJ2(-18.016,-7.315) AJ39(18.016,-8.23) AJ40(18.931,-8.23) AK1(-18.931,-8.23) AK2(-18.016,-8.23) AK39(18.016,-9.144) AK40(18.931,-9.144) AL1(-18.931,-9.144) AL2(-18.016,-9.144) AL39(18.016,-10.058) AL40(18.931,-10.058) AM1(-18.931,-10.058) AM2(-18.016,-10.058) AM39(18.016,-10.973) AM40(18.931,-10.973) AN1(-18.931,-10.973) AN2(-18.016,-10.973) AN39(18.016,-11.887) AN40(18.931,-11.887) AP1(-18.931,-11.887) AP2(-18.016,-11.887) AP39(18.016,-12.802) AP40(18.931,-12.802) AR1(-18.931,-12.802) AR2(-18.016,-12.802) AR39(18.016,-13.716) AR40(18.931,-13.716) AT1(-18.931,-13.716) AT2(-18.016,-13.716) AT39(18.016,-14.63) AU2(-18.016,-14.63) E1(-18.931,14.63) E2(-18.016,14.63) F1(-18.931,13.716) F2(-18.016,13.716) F3(-17.102,13.716) G1(-18.931,12.802) G2(-18.016,12.802) H1(-18.931,11.887) H2(-18.016,11.887) H3(-17.102,11.887) J1(-18.931,10.973) J2(-18.016,10.973) K1(-18.931,10.058) K2(-18.016,10.058) K3(-17.102,10.058) L1(-18.931,9.144) L2(-18.016,9.144) M1(-18.931,8.23) M2(-18.016,8.23) M3(-17.102,8.23) N1(-18.931,7.315) N2(-18.016,7.315) P1(-18.931,6.401) P2(-18.016,6.401) P3(-17.102,6.401) R1(-18.931,5.486) R2(-18.016,5.486) T1(-18.931,4.572) T2(-18.016,4.572) T3(-17.102,4.572) U1(-18.931,3.658) U2(-18.016,3.658) U3(-17.102,3.658) V1(-18.931,2.743) V2(-18.016,2.743) V3(-17.102,2.743) W1(-18.931,1.829) W2(-18.016,1.829) W3(-17.102,1.829) Y3(-17.102,0.914) Y4(-16.187,0.914)
